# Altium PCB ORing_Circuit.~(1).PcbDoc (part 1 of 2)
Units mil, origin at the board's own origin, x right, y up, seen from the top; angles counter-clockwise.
Board outline 1338.58 x 1378.07 mil, 8 copper layers (Top Layer, Layer 2, Layer 3, Layer 4, Layer 5, Layer 6, Layer 7, Bottom Layer), stack 50.047 mil thick; 34 components, 15 nets, 290 pads, 1023 vias.
Unrouted connection lines stored in the file: 1.
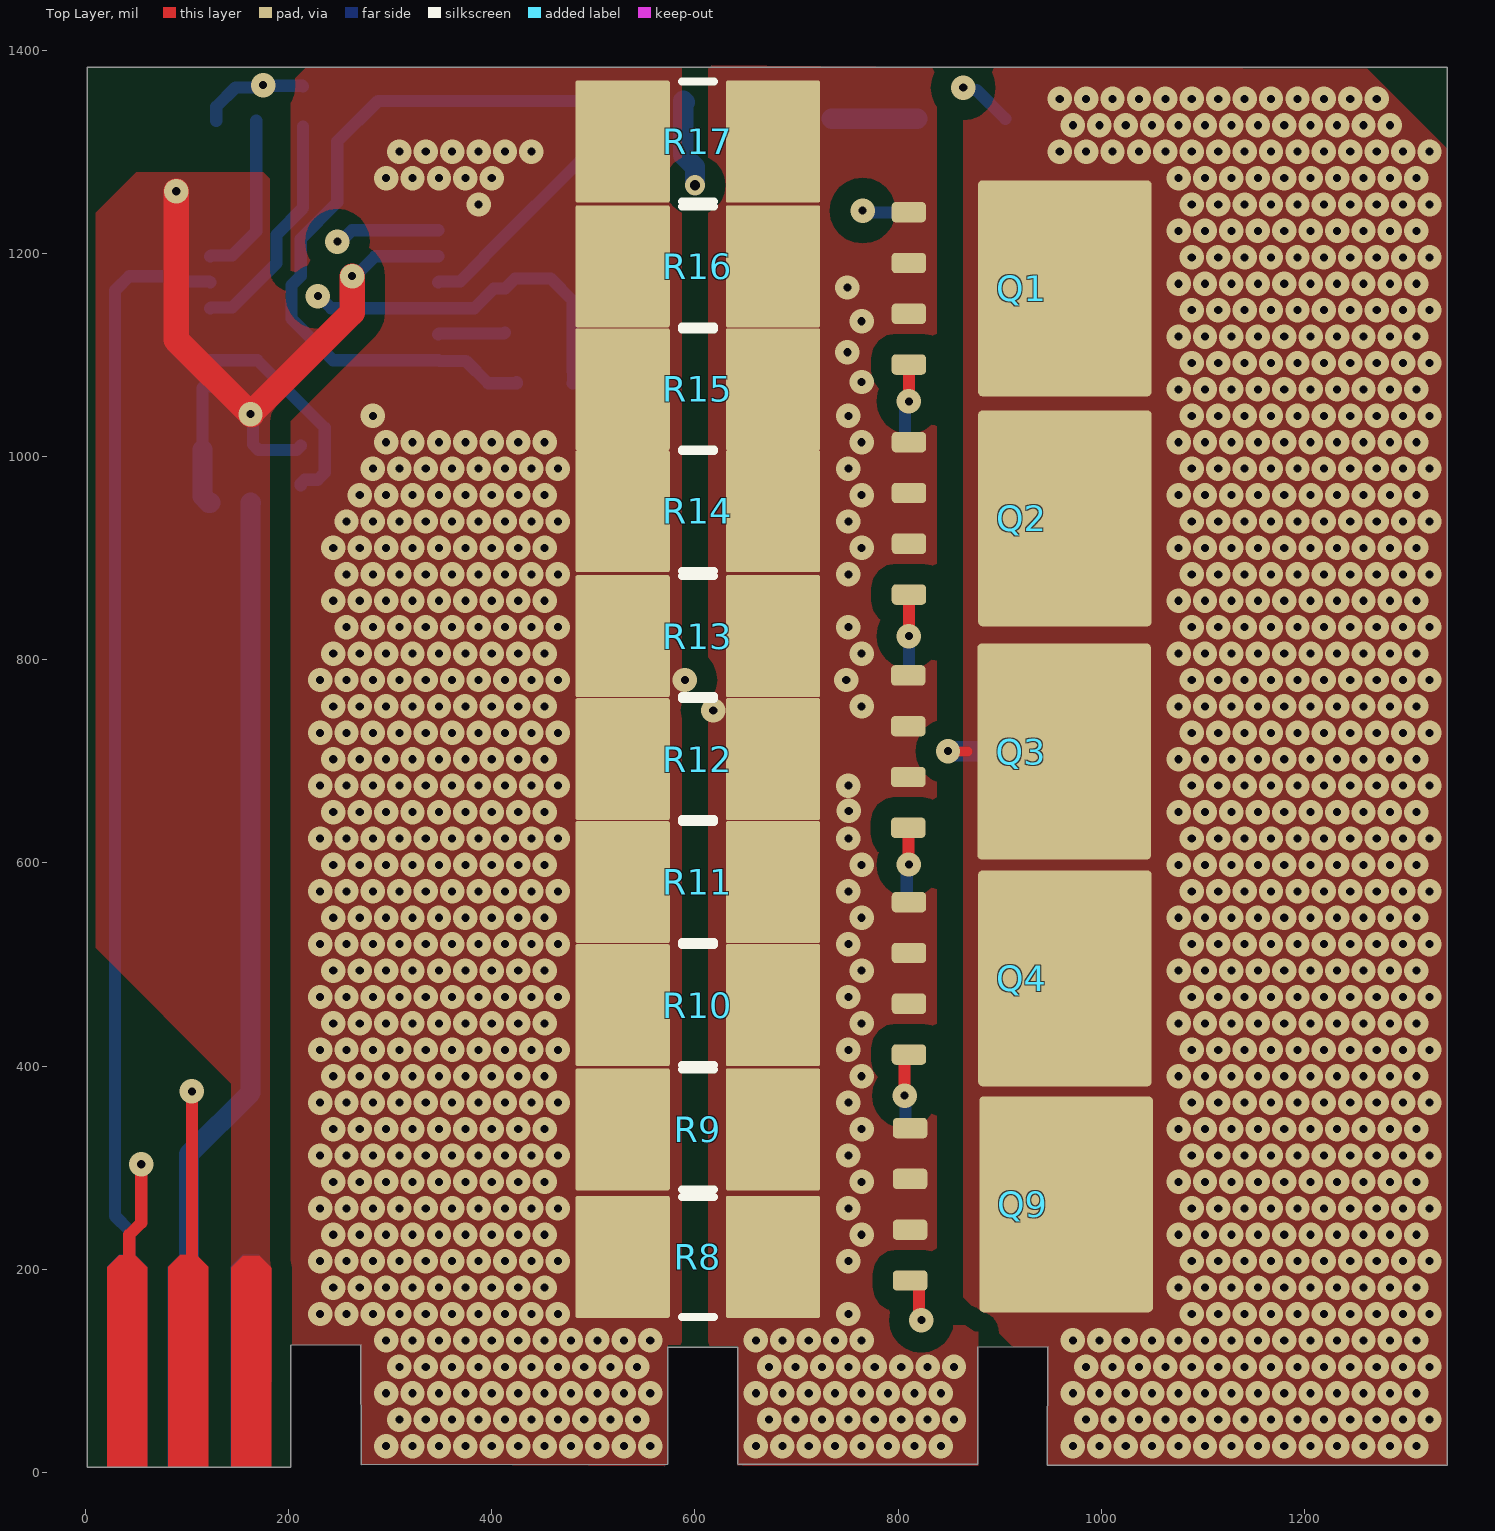
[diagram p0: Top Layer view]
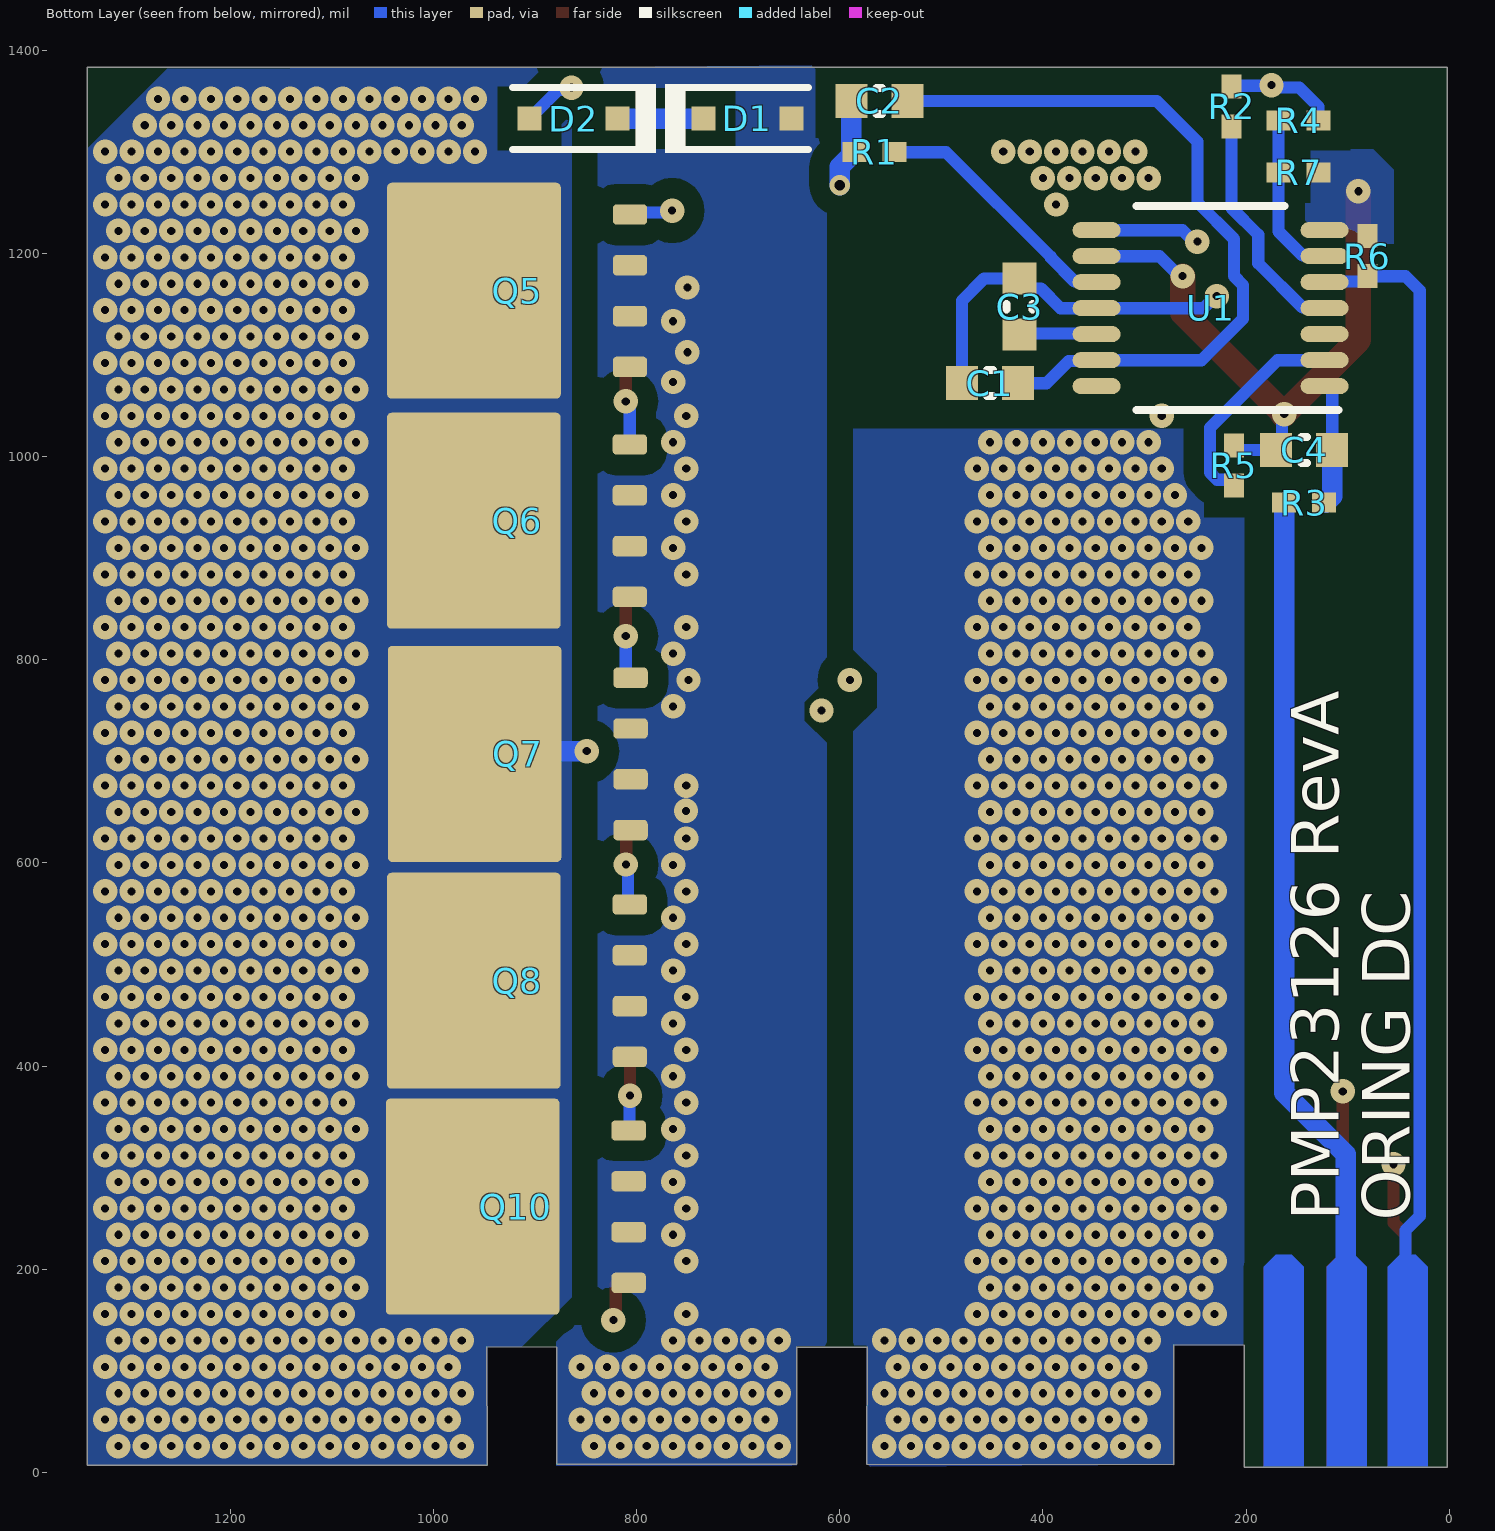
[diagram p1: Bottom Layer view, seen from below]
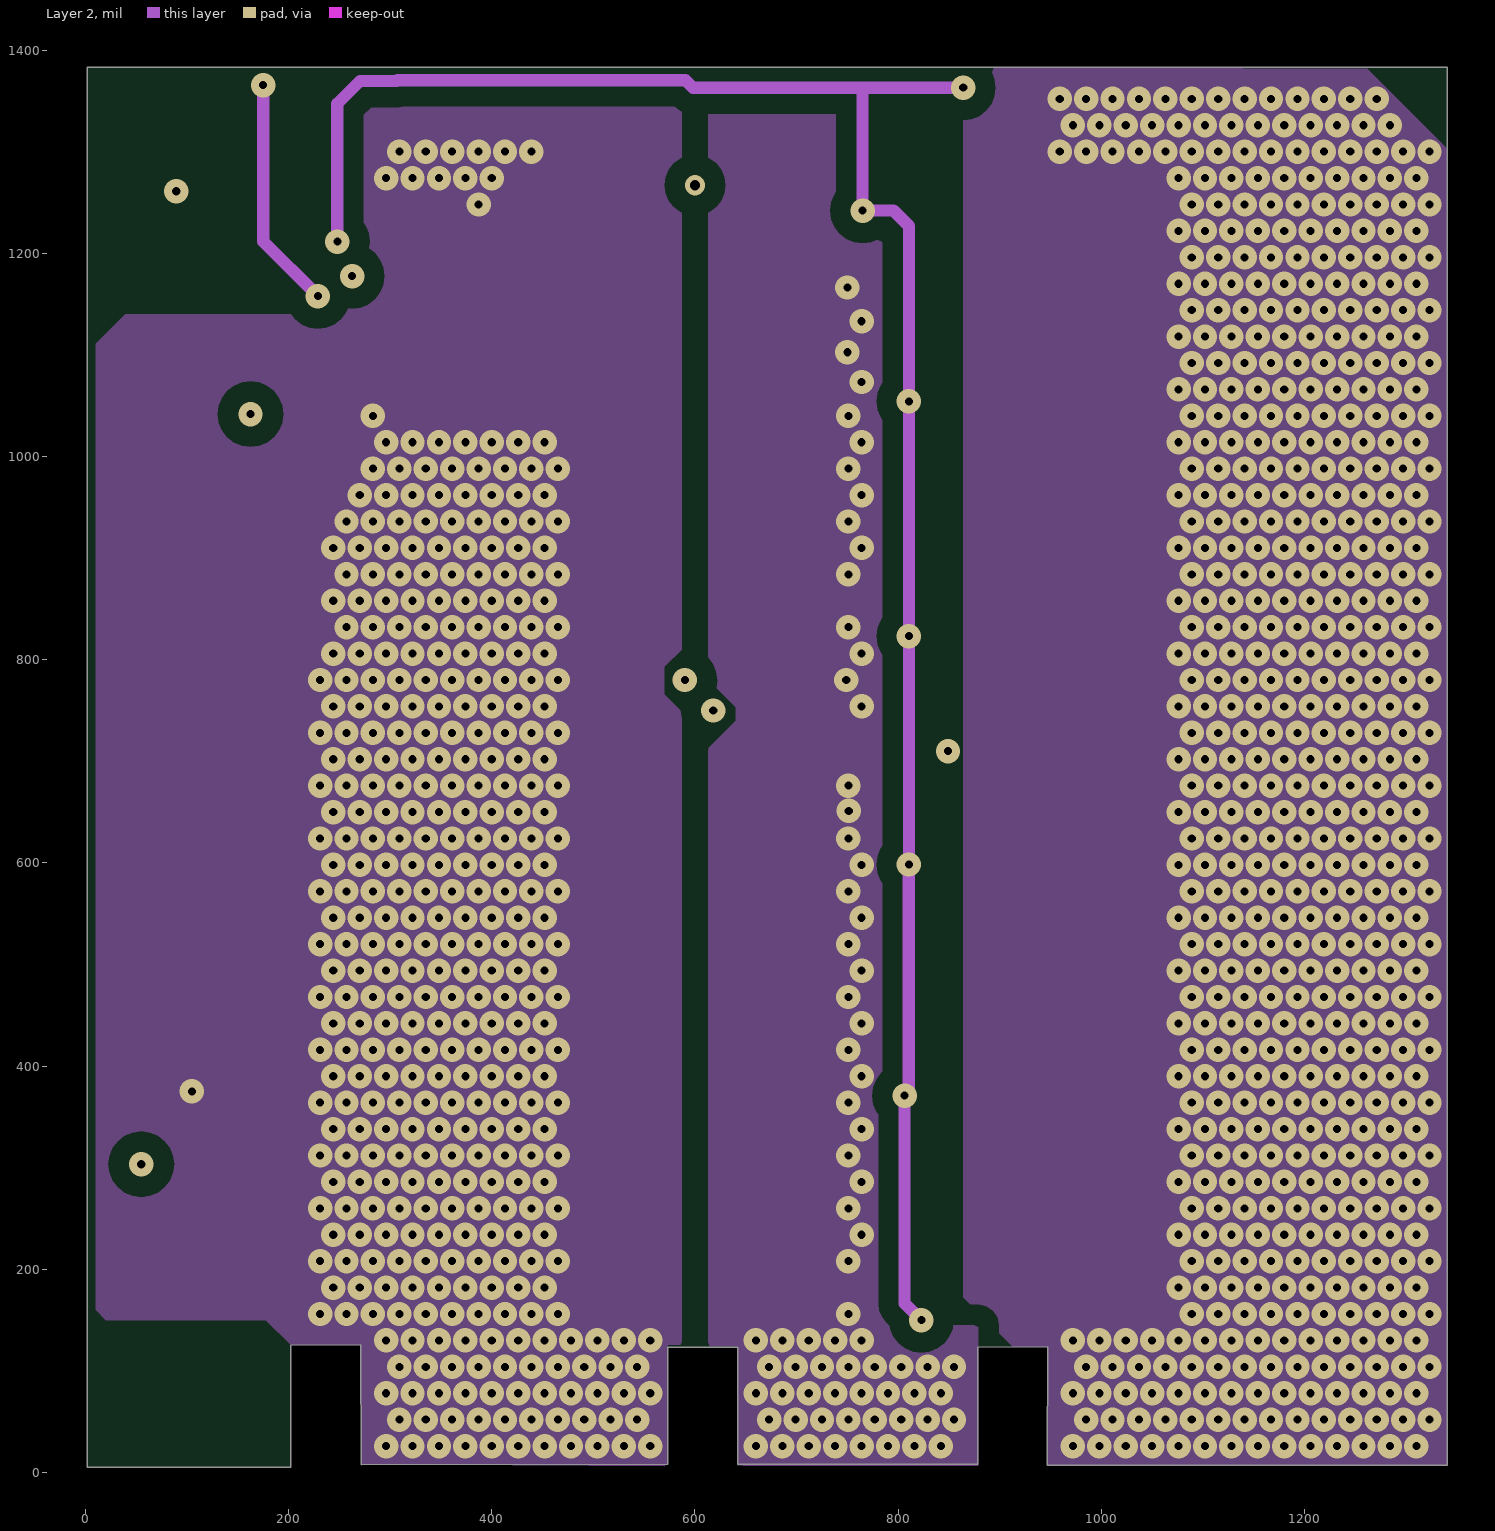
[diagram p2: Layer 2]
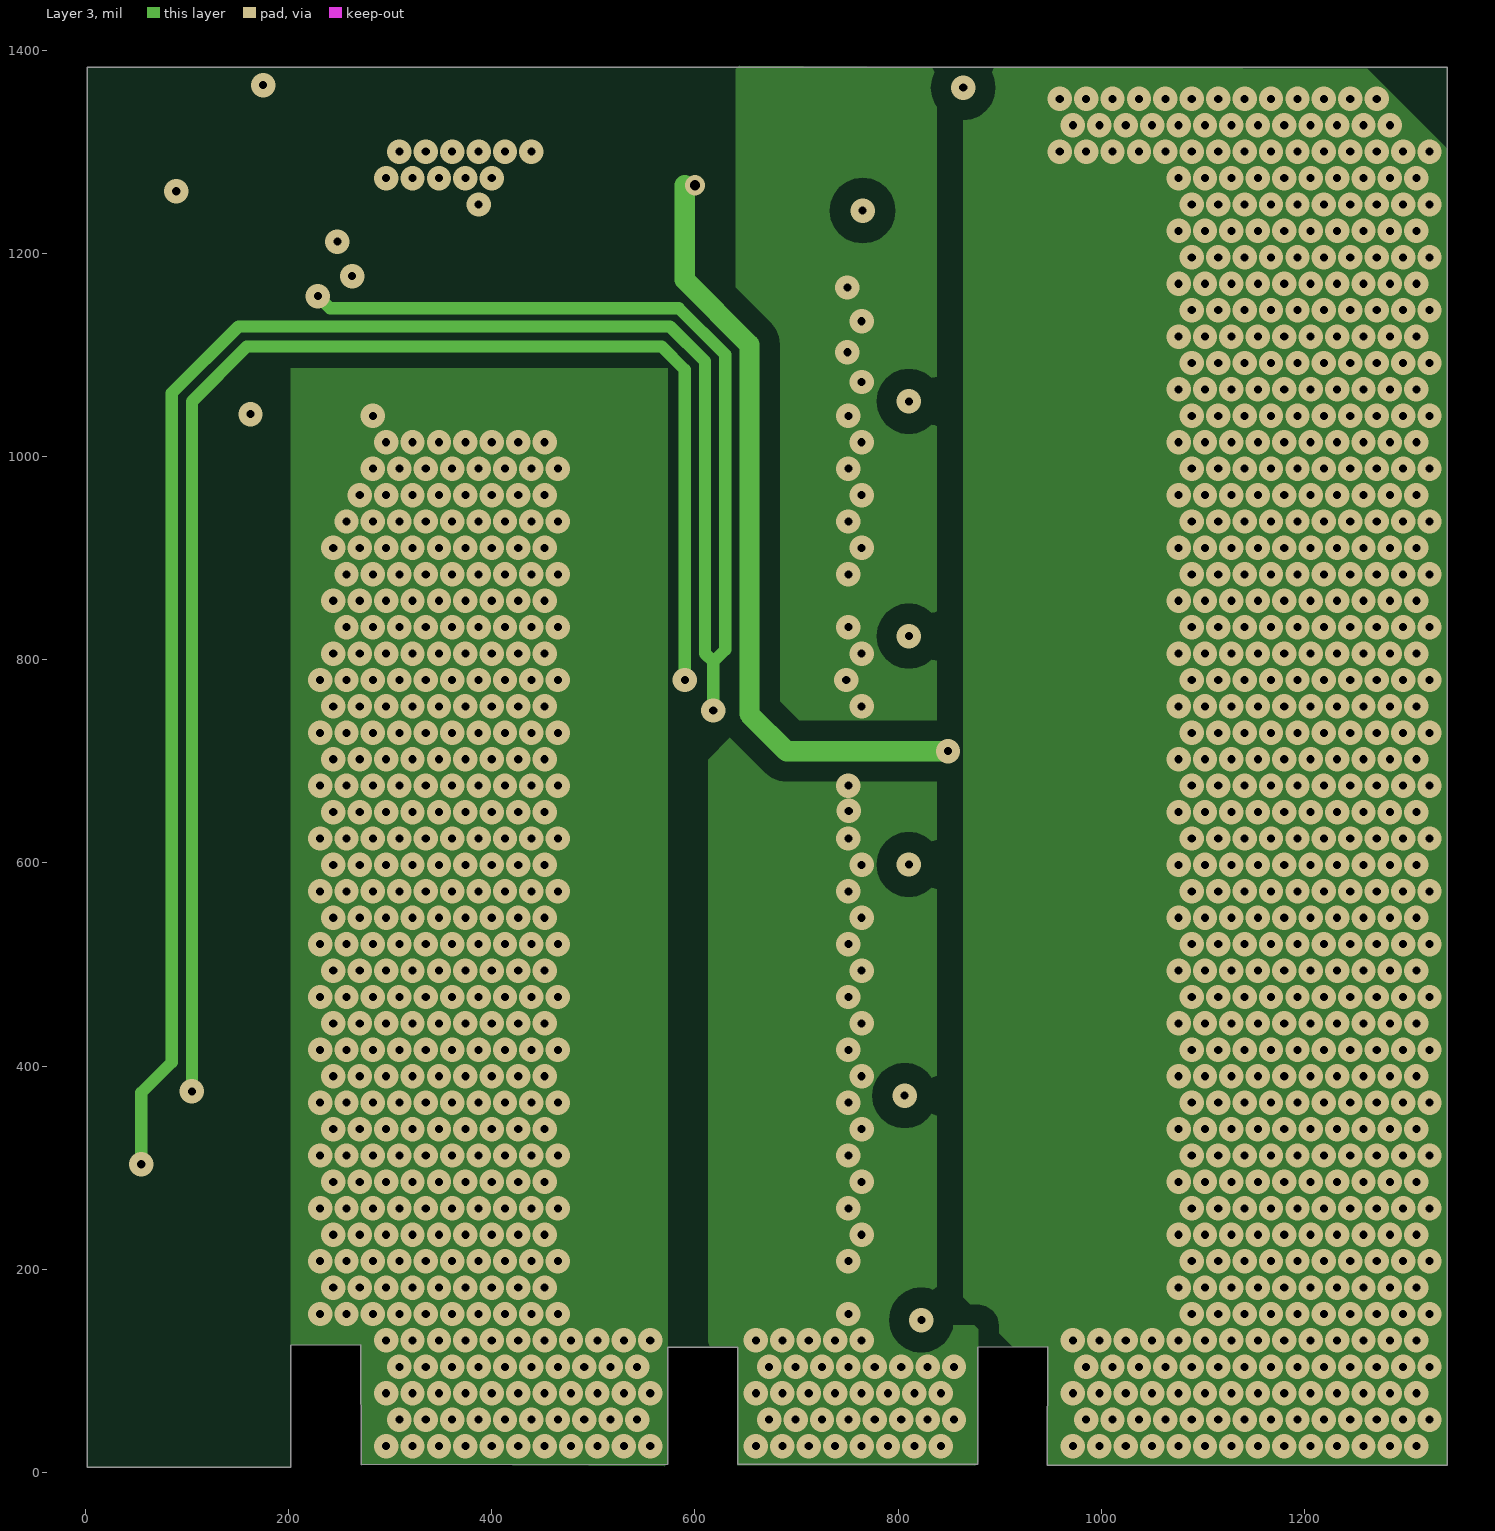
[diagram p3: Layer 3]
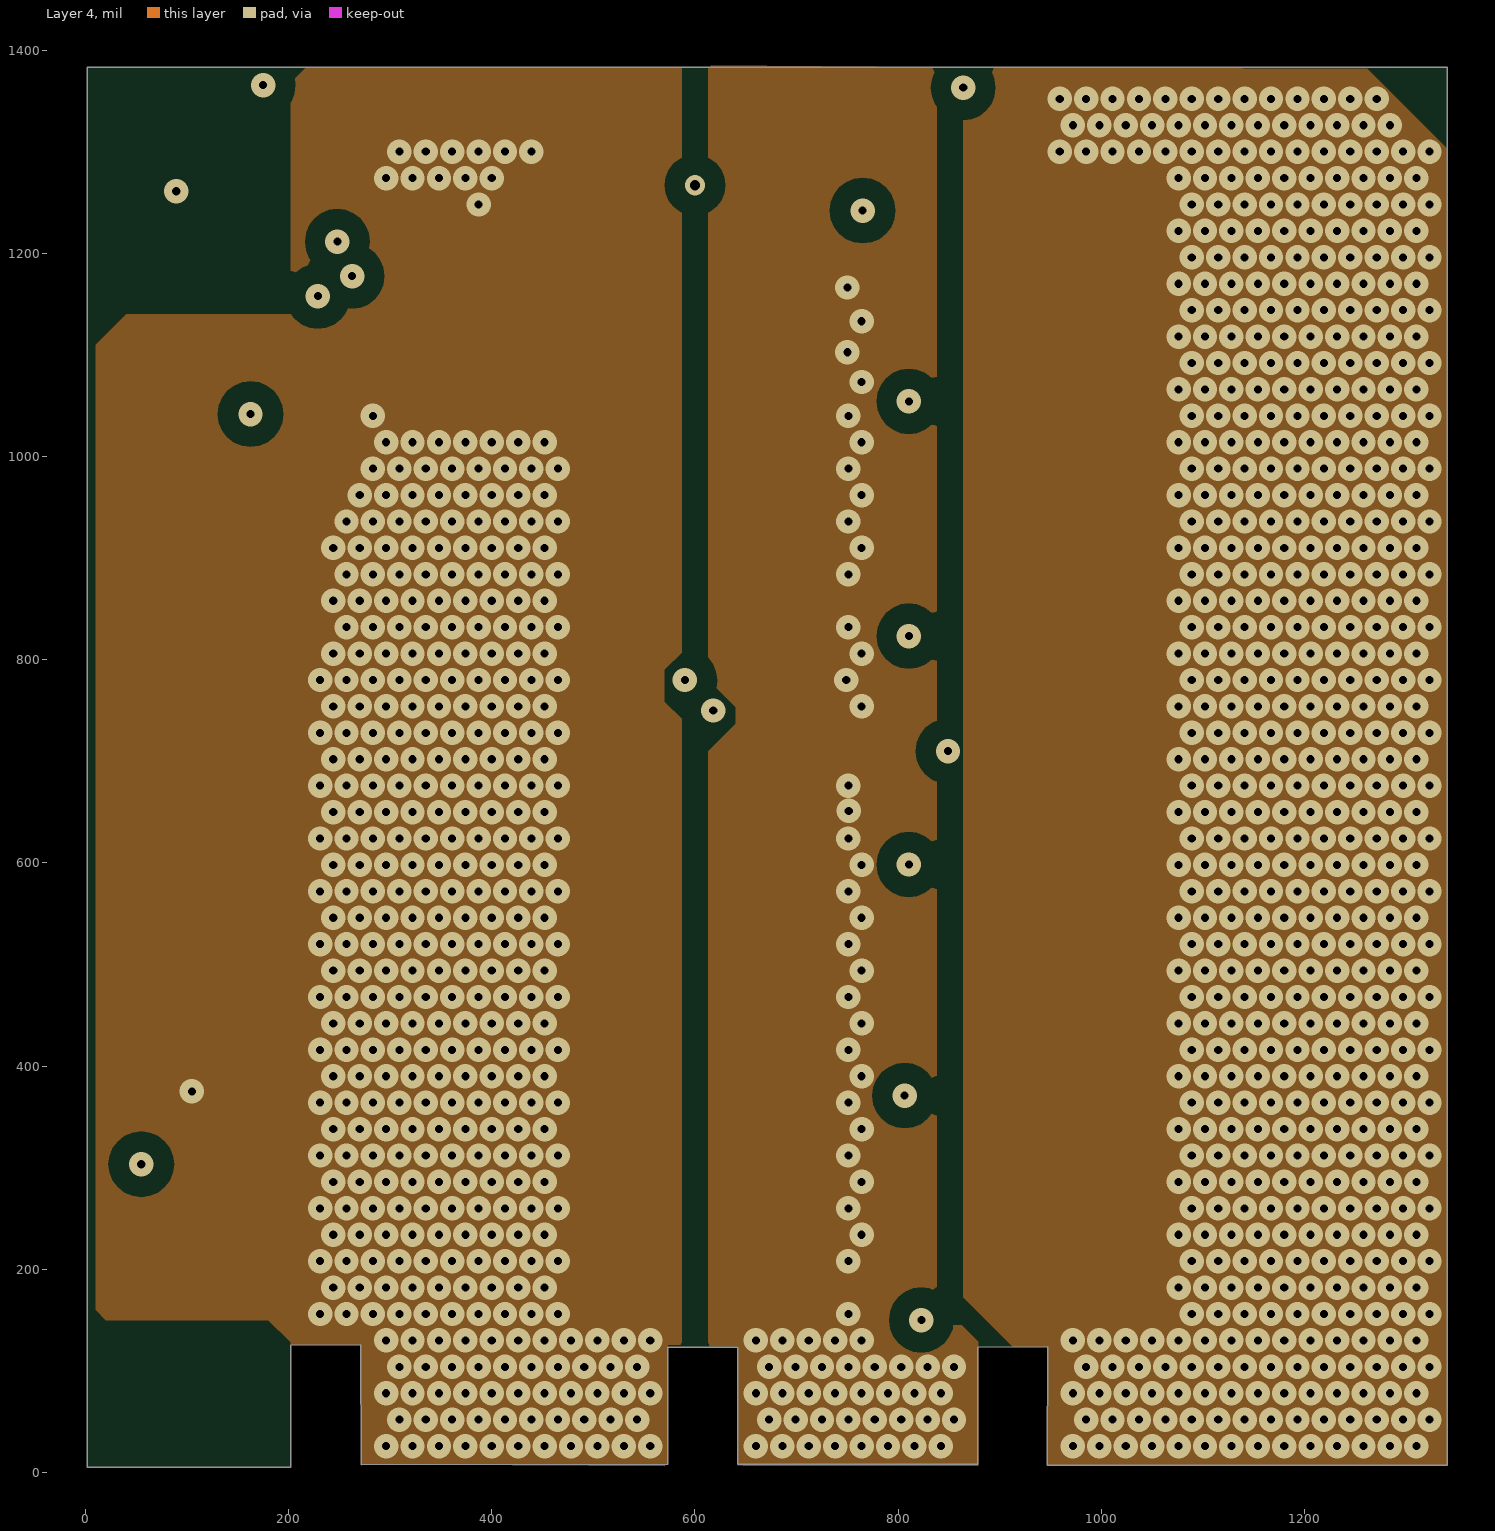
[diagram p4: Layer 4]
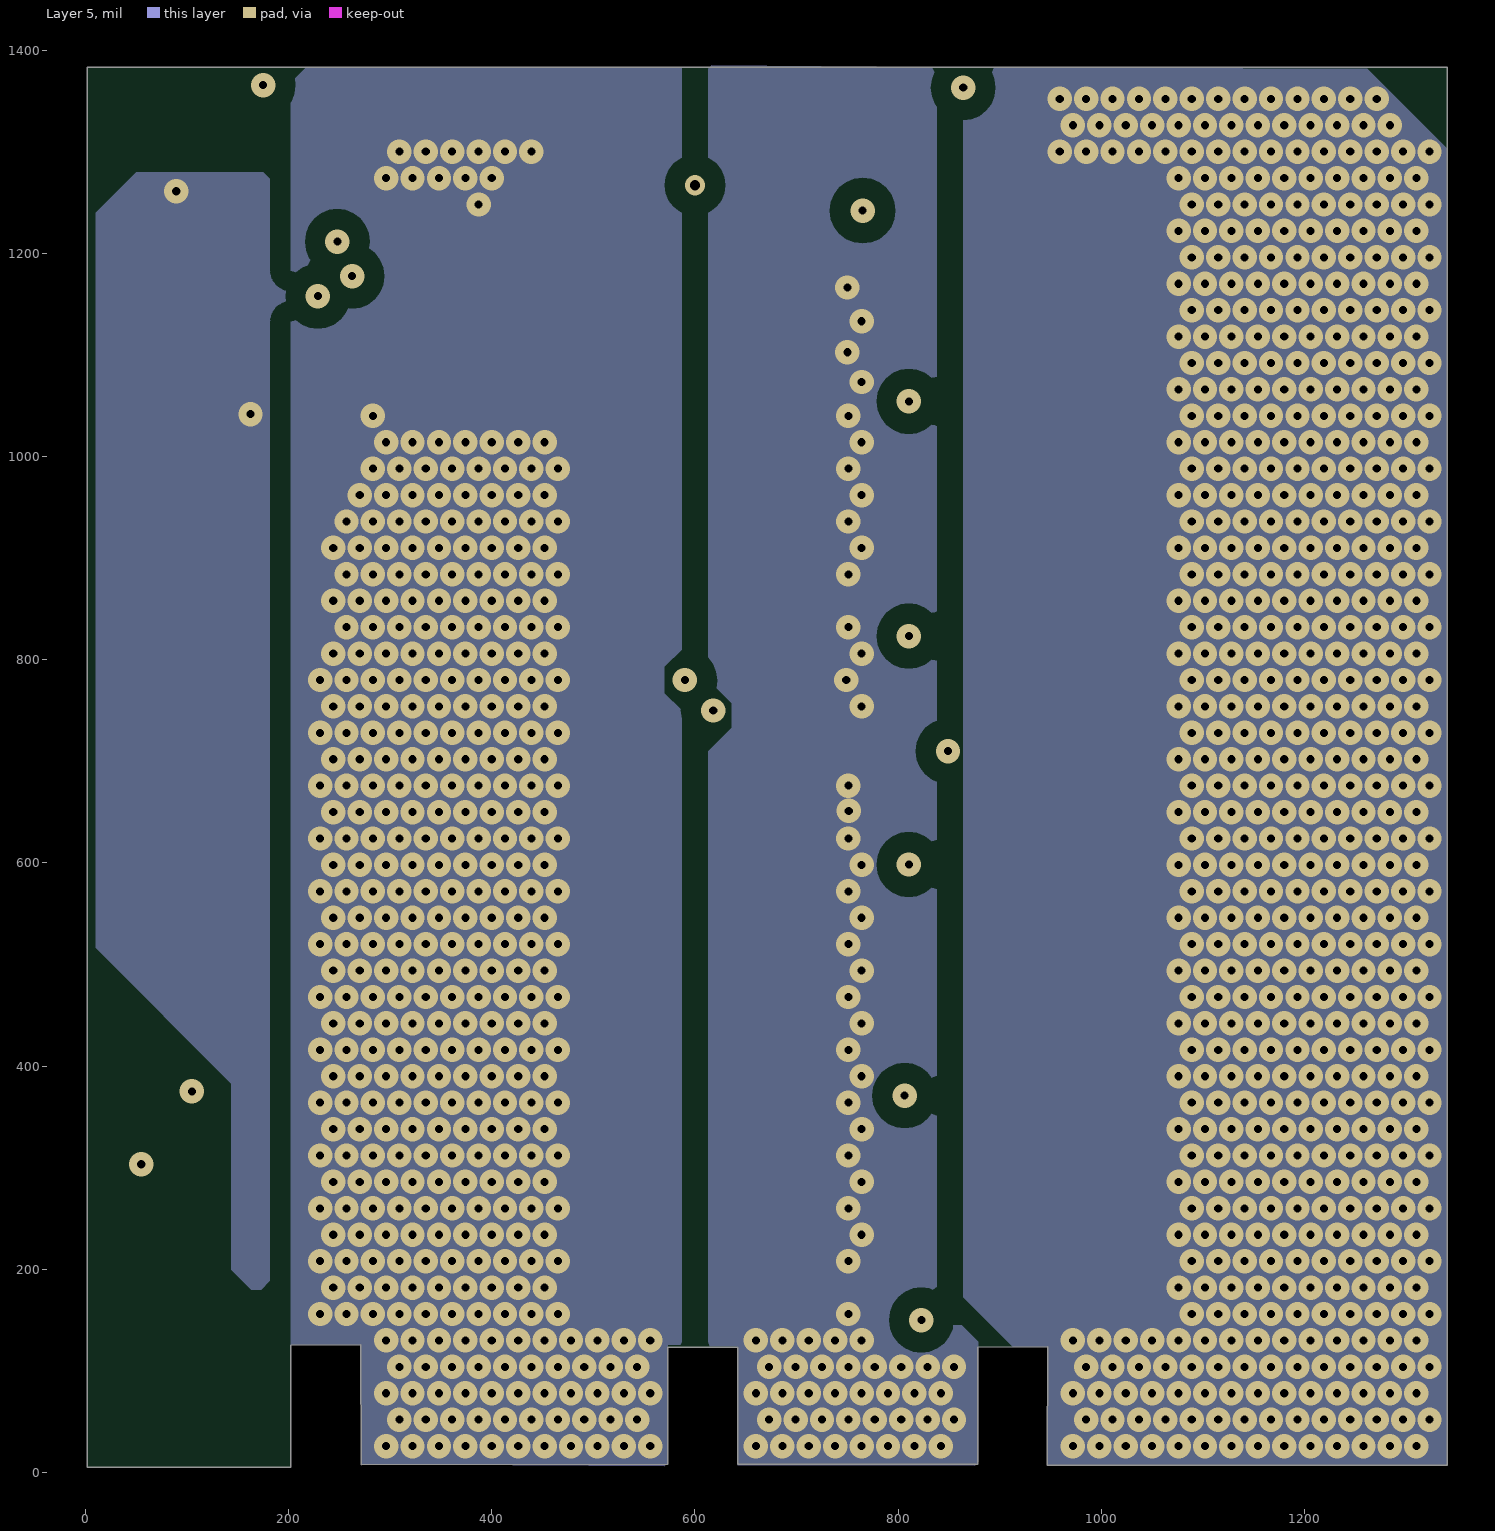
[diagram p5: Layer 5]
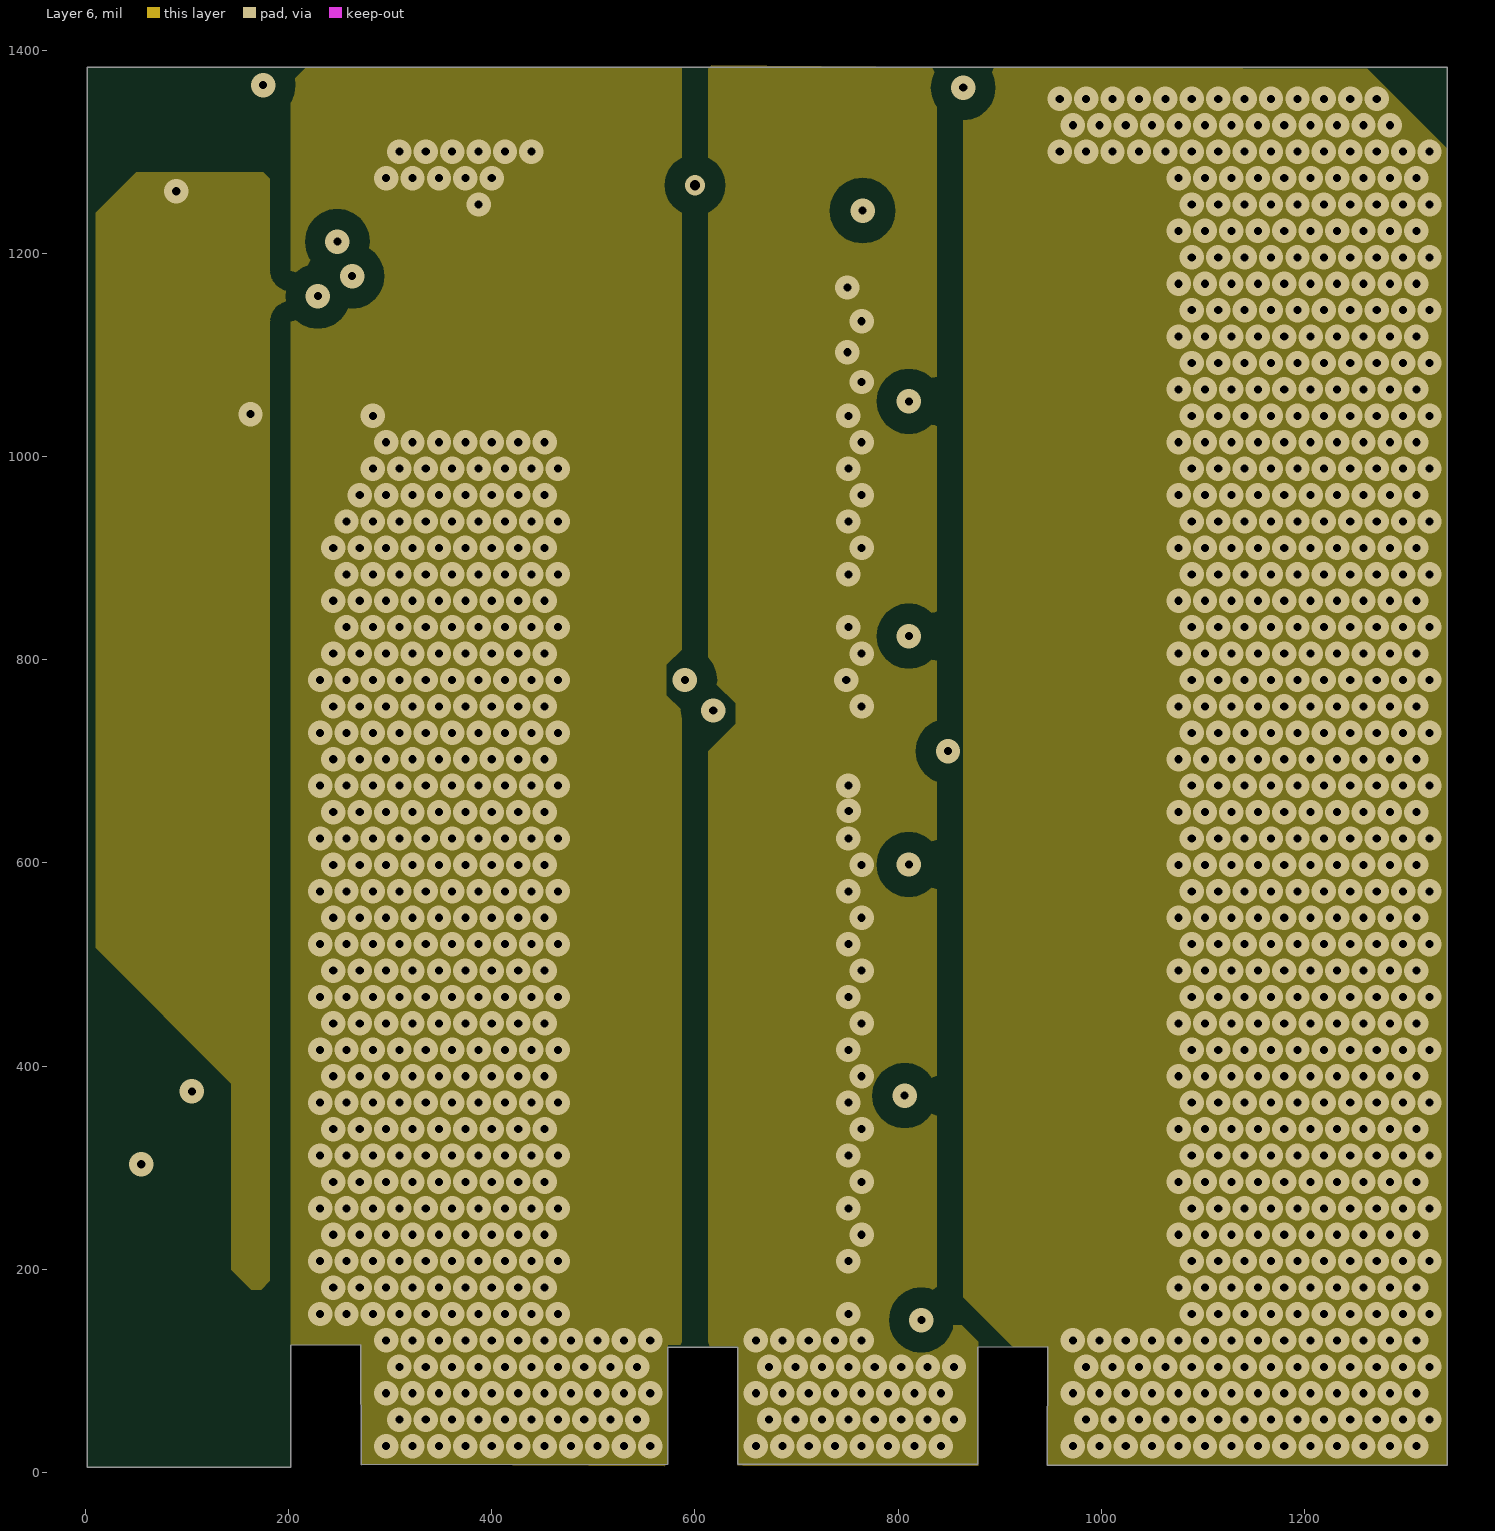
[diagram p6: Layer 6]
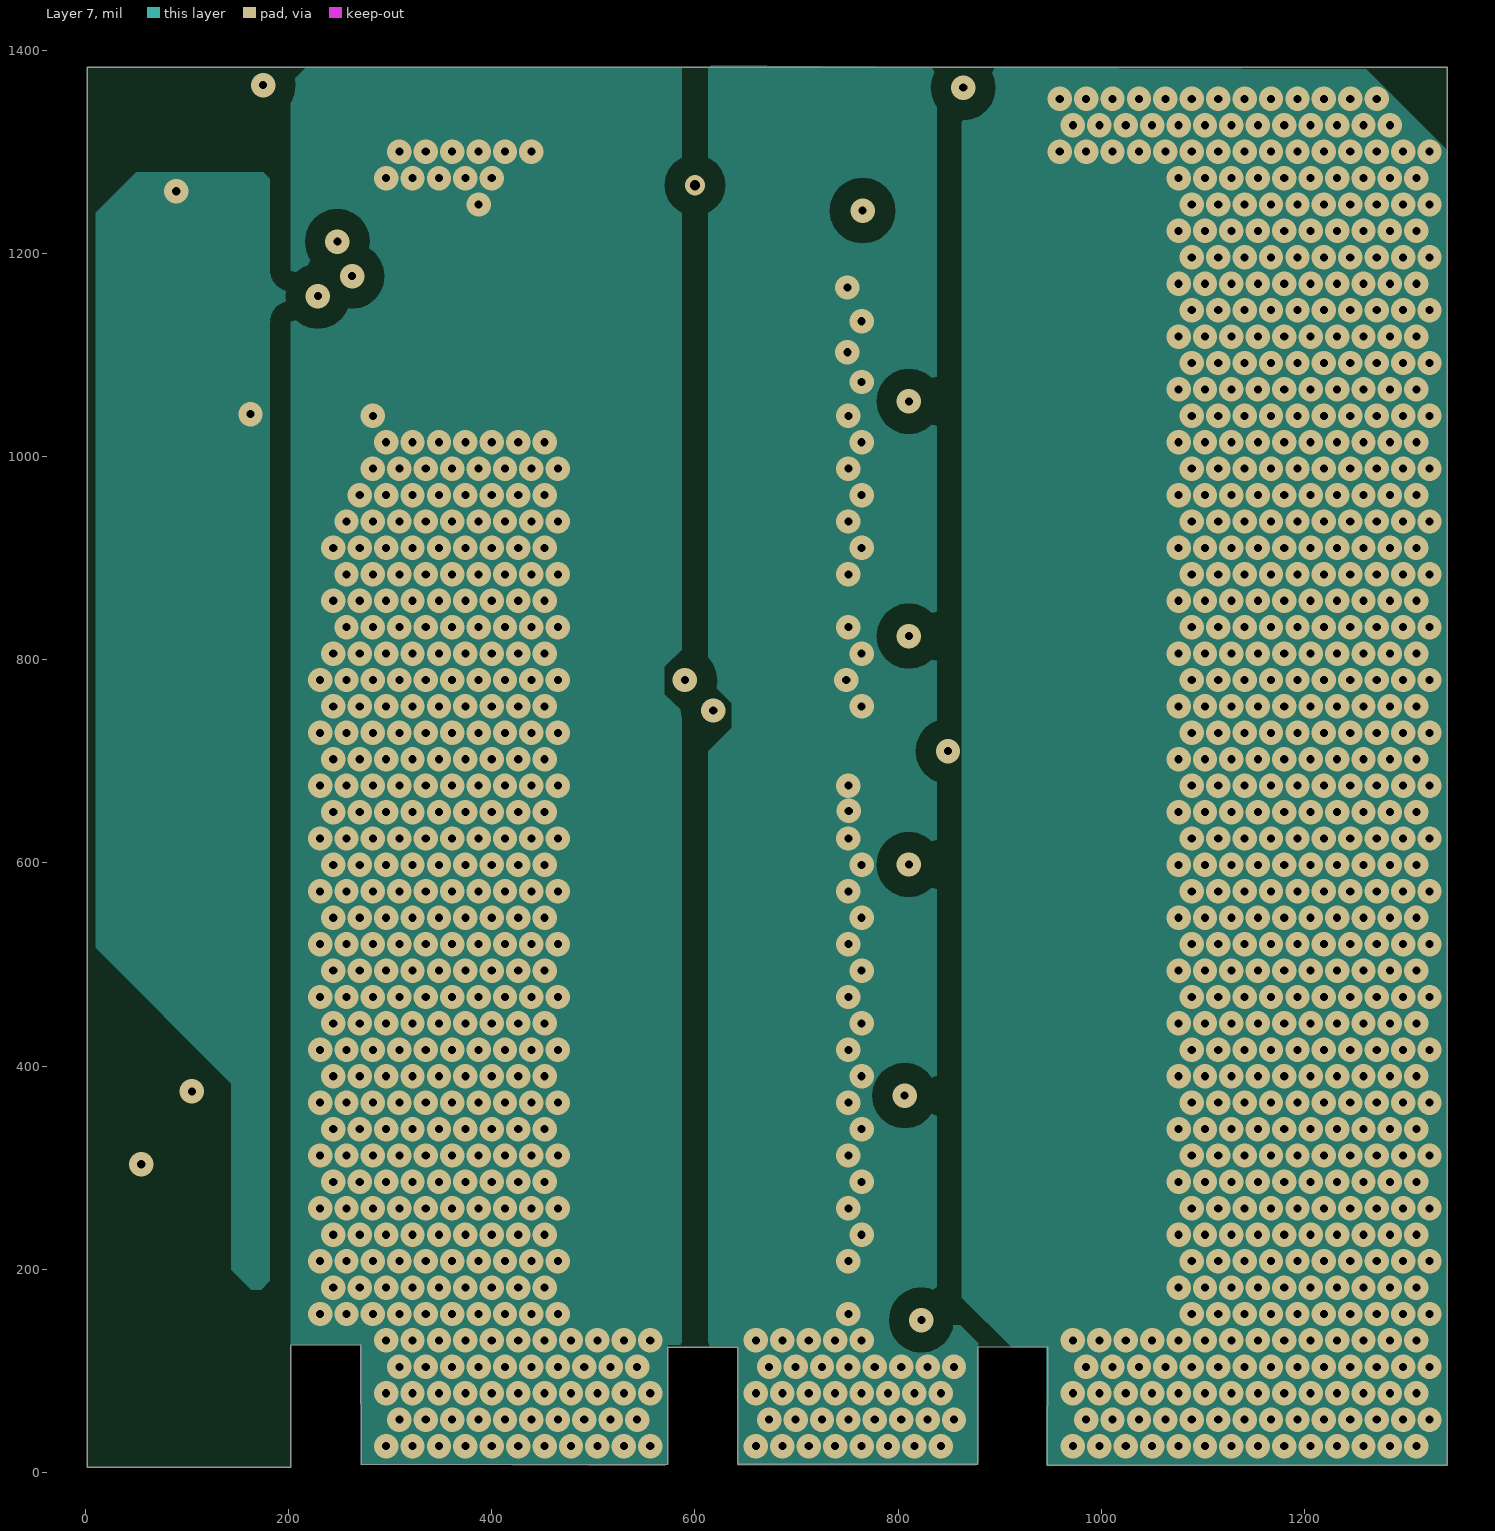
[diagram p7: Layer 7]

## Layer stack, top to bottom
Top Solder: solder mask 0.4, Solder Resist, Dk 3.5
Top Layer: signal copper 2.7559
Dielectric 1: core 4, Core-009, Dk 4.5
Layer 2: signal copper 2.7559
Dielectric 3: core 4, Core-009, Dk 4.5
Layer 3: signal copper 2.7559
Dielectric 5: core 4, Core-009, Dk 4.5
Layer 4: signal copper 2.7559
Dielectric1: core 4, Core-009, Dk 4.5
Layer 5: signal copper 2.7559
Dielectric 6: core 4, Core-009, Dk 4.5
Layer 6: signal copper 2.7559
Dielectric 4: core 4, Core-009, Dk 4.5
Layer 7: signal copper 2.7559
Dielectric 2: core 4, Core-009, Dk 4.5
Bottom Layer: signal copper 2.7559
Bottom Solder: solder mask 0.4, Solder Resist, Dk 3.5

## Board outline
1.94,5 202,5 202,125.23 271,125.49 271.31,7.69 573.42,7.94 573.11,123.48 642.11,123.48 642.11,7.94 878.33,7.94 878.33,123.48 947.33,123.74 946.83,7.25 1340.53,7 1340.53,1383.07 1.94,1383.07

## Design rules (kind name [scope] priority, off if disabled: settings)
AcuteAngle [All] p1: minimum=4.50000000000000E+0001 checktracksonly=FALSE
AssemblyTestPointUsage [All] p1: valid=2
Clearance Clearance_2 [InNetClass('HV') vs Not InNetClass('HV')] p1: gap=60 ignorepadtopadclearanceinfootprint=TRUE except(0: Arc-Hole Track-Hole SMDPad-Hole THPad-Hole Via-Hole Fill-Hole Poly-Hole Region-Hole Text-Hole)
Clearance Clearance_1 [InNetClass('MV') vs Not InNetClass('MV')] p2: gap=40 ignorepadtopadclearanceinfootprint=TRUE
Clearance Clearance_Keepouts [((IsTrack Or IsArc) And Not InPoly) And IsFree and IsKeepOut vs ((IsTrack Or IsArc) And Not InPoly) And IsFree and IsKeepOut] p3: gap=0 ignorepadtopadclearanceinfootprint=FALSE
Clearance Clearance_BoardEdge_MountingHoles [OnCopper and InComponentClass('Mounting Holes') vs IsKeepOut] p4: gap=40 ignorepadtopadclearanceinfootprint=FALSE except(0: Arc-Hole Track-Hole SMDPad-Hole THPad-Hole Via-Hole Fill-Hole Poly-Hole Region-Hole Text-Hole)
Clearance Clearance_BoardEdge_Poly [OnCopper and InPoly vs IsKeepOut] p5: gap=25 ignorepadtopadclearanceinfootprint=FALSE except(0: Arc-Hole Track-Hole SMDPad-Hole THPad-Hole Via-Hole Fill-Hole Poly-Hole Region-Hole Text-Hole)
Clearance Clearance_BoardEdge [OnCopper and Not InComponentClass('Logo') and not InComponentClass('FiducialMark') and not InRegion(1000,500,4000,800) and Not IsKeepout vs IsKeepOut] p6: gap=75 ignorepadtopadclearanceinfootprint=FALSE except(0: Arc-Hole Track-Hole SMDPad-Hole THPad-Hole Via-Hole Fill-Hole Poly-Hole Region-Hole Text-Hole)
Clearance Clearance_Poly [InPolygon] p7: gap=20 ignorepadtopadclearanceinfootprint=FALSE except(0: Arc-Hole Track-Hole SMDPad-Hole THPad-Hole Via-Hole Fill-Hole Poly-Hole Region-Hole Text-Hole)
Clearance [All] p8: gap=7.87 ignorepadtopadclearanceinfootprint=FALSE except(0: Arc-SMDPad Arc-Hole Track-Hole SMDPad-Hole THPad-Hole Via-Hole Fill-Hole Poly-Hole Region-Hole Text-Hole)
ComponentClearance ComponentClearance_MountingHoles_FiducialMarks [InComponentClass('Mounting Holes') vs InComponentClass('FiducialMark')] p1: gap=20 collisioncheckmode=3 verticalgap=7 showdistances=FALSE
ComponentClearance ComponentClearance_Shunt [InComponentClass('Header') vs InComponentClass('Shunt')] p2: gap=0 collisioncheckmode=3 verticalgap=0 showdistances=FALSE
ComponentClearance ComponentClearance_Logo [InComponentClass('Logo')] p3: gap=5 collisioncheckmode=3 verticalgap=10 showdistances=FALSE
ComponentClearance ComponentClearance_ScrewToNut [(HasFootprint('KEYSTONE_4824')) vs (HasFootprint('Keystone_1903C'))] p4: gap=0 collisioncheckmode=3 verticalgap=0 showdistances=FALSE
ComponentClearance ComponentClearance_MountingHoles [InComponentClass('Mounting Holes')] p5: gap=20 collisioncheckmode=3 verticalgap=7 showdistances=FALSE
ComponentClearance ComponentClearance_SmallPassives [HasFootprint('0201*') or HasFootprint('0402*') or HasFootprint('0508') or HasFootprint('0603*') or HasFootprint('0612') or HasFootprint('0805*') or HasFootprint('0815*') or HasFootprint('0830*') or HasFootprint('1206*') or HasFootprint('1210*') or HasFootprint('1808*') or HasFootprint('1812*') or HasFootprint('1825*') or HasFootprint('2010*') or HasFootprint('2220*') or HasFootprint('2225*') or HasFootprint('2512*') or HasFootprint('2728*') or HasFootprint('3518*') vs HasFootprint('0201*') or HasFootprint('0402*') or HasFootprint('0508') or HasFootprint('0603*') or HasFootprint('0612') or HasFootprint('0805*') or HasFootprint('0815*') or HasFootprint('0830*') or HasFootprint('1206*') or HasFootprint('1210*') or HasFootprint('1808*') or HasFootprint('1812*') or HasFootprint('1825*') or HasFootprint('2010*') or HasFootprint('2220*') or HasFootprint('2225*') or HasFootprint('2512*') or HasFootprint('2728*') or HasFootprint('3518*')] p6: gap=20 collisioncheckmode=3 verticalgap=20 showdistances=FALSE
ComponentClearance ComponentClearance_THtoSMT [IsThruComponent vs IsSMTComponent] p7: gap=10 collisioncheckmode=3 verticalgap=7 showdistances=FALSE
ComponentClearance ComponentClearance_THtoTH [IsThruComponent vs IsThruComponent] p8: gap=10 collisioncheckmode=3 verticalgap=7 showdistances=FALSE
ComponentClearance [All] p9: gap=10 collisioncheckmode=3 verticalgap=7 showdistances=FALSE
DiffPairsRouting [All] p1: maxlimit=100 minlimit=10 mostfreqgap=10 toplayer_minwidth=15 toplayer_maxwidth=15 toplayer_prefwidth=15 midlayer1_minwidth=15 midlayer1_maxwidth=15 midlayer1_prefwidth=15 midlayer2_minwidth=15 midlayer2_maxwidth=15 midlayer2_prefwidth=15 midlayer3_minwidth=15 midlayer3_maxwidth=15 midlayer3_prefwidth=15 midlayer4_minwidth=15 midlayer4_maxwidth=15 midlayer4_prefwidth=15 midlayer5_minwidth=15 midlayer5_maxwidth=15 midlayer5_prefwidth=15 midlayer6_minwidth=15 midlayer6_maxwidth=15 midlayer6_prefwidth=15 bottomlayer_minwidth=15 bottomlayer_maxwidth=15 bottomlayer_prefwidth=15 maxuncoupledlength=1000
FabricationTestPointUsage TestPointUsage [All] p1: valid=2 allowmultiple=FALSE
FabricationTestpoint Testpoint [All] p1: side=3 testpointundercomponent=TRUE minsize=40 maxsize=100 preferedsize=60 minholesize=0 maxholesize=40 preferedholesize=32 testpointgrid=1 allowsidetop=TRUE allowsidebottom=TRUE usegrid=TRUE gridtolerance=0.01
FanoutControl Fanout_LCC [IsLCC] p1: bgadir=Out bgaviamode=Centered fanoutstyle=Auto fanoutdirection=Alternating viagrid=1 // Fanout_LCC (Default Rule)
FanoutControl Fanout_BGA [IsBGA] p2: bgadir=Out bgaviamode=Centered fanoutstyle=Auto fanoutdirection=Alternating viagrid=1 // Fanout_BGA (Default Rule)
FanoutControl Fanout_Default [All] p4: bgadir=Out bgaviamode=Centered fanoutstyle=Auto fanoutdirection=Alternating viagrid=1 // Fanout_Default (Default Rule)
FanoutControl Fanout_Small [(CompPinCount < 5)] p5: bgadir=Out bgaviamode=Centered fanoutstyle=Auto fanoutdirection=OutThenIn viagrid=1 // Fanout_Small (Default Rule)
Height [All] p1: minheight=0 maxheight=3000 prefheight=500
HoleSize [All] p1: absolutevalues=TRUE maxlimit=501 minlimit=7 maxpercent=80.000 minpercent=20.000
MinimumAnnularRing MinimumAnnularRing_ThermalPadVias [IsVia and InAnyComponent] p1: minimumring=5.91
MinimumAnnularRing [All] p2: minimumring=5
MinimumSolderMaskSliver MinimumSolderMaskSliver_Logo [InComponentClass('Logo') vs InComponentClass('Logo')] p1: minsoldermaskwidth=0.7
MinimumSolderMaskSliver [All] p2: minsoldermaskwidth=1
PlaneConnect [All] p1: planeconnectstyle=Direct reliefexpansion=10 reliefentries=4 reliefconductorwidth=10 reliefairgap=10
PolygonConnect PolygonConnect_16 [All vs IsNamedPolygon('C106_2') Or  IsNamedPolygon('Vout') Or  IsNamedPolygon('IN+') Or  IsNamedPolygon('Q203_5') Or  IsNamedPolygon('IN+') Or  IsNamedPolygon('Q201_5') Or  IsNamedPolygon('C108_2') Or  IsNamedPolygon('SGND') Or  IsNamedPolygon('IN+') Or  IsNamedPolygon('SGND') Or  IsNamedPolygon('Q203_5') Or  IsNamedPolygon('IN+') Or  IsNamedPolygon('SGND') Or  IsNamedPolygon('GND') Or  IsNamedPolygon('C113_2') Or  IsNamedPolygon('C107_2') Or  IsNamedPolygon('C107_2') Or  IsNamedPolygon('Vout') Or  IsNamedPolygon('SIGNAL_LAYER_1_GND_P074') Or  IsNamedPolygon('HV') Or  IsNamedPolygon('C108_2') Or  IsNamedPolygon('C103_2') Or  IsNamedPolygon('Q201_5') Or  IsNamedPolygon('Vout') Or  IsNamedPolygon('C109_2') Or  IsNamedPolygon('Q201_5') Or  IsNamedPolygon('GND') Or  IsNamedPolygon('C107_2') Or  IsNamedPolygon('C102_1') Or  IsNamedPolygon('GND') Or  IsNamedPolygon('SGND') Or  IsNamedPolygon('HS') Or  IsNamedPolygon('Q203_5') Or  IsNamedPolygon('Q201_5') Or  IsNamedPolygon('Q203_5')] p1: connectstyle=Direct reliefconductorwidth=10 reliefentries=4 polygonreliefangle="90 Angle" airgapwidth=10
PolygonConnect PolygonConnect_15 [All vs IsNamedPolygon('C109_2') Or  IsNamedPolygon('C107_2') Or  IsNamedPolygon('HV') Or  IsNamedPolygon('Q203_5') Or  IsNamedPolygon('C107_2') Or  IsNamedPolygon('HS') Or  IsNamedPolygon('Q201_5') Or  IsNamedPolygon('Q203_5') Or  IsNamedPolygon('C106_2') Or  IsNamedPolygon('C108_2') Or  IsNamedPolygon('Vout') Or  IsNamedPolygon('Q203_5') Or  IsNamedPolygon('C108_2') Or  IsNamedPolygon('C113_2') Or  IsNamedPolygon('Q203_5') Or  IsNamedPolygon('Q201_5') Or  IsNamedPolygon('C107_2') Or  IsNamedPolygon('C102_1') Or  IsNamedPolygon('SGND') Or  IsNamedPolygon('GND') Or  IsNamedPolygon('SGND') Or  IsNamedPolygon('GND') Or  IsNamedPolygon('IN+') Or  IsNamedPolygon('IN+') Or  IsNamedPolygon('Q201_5') Or  IsNamedPolygon('Q201_5') Or  IsNamedPolygon('SGND') Or  IsNamedPolygon('SGND') Or  IsNamedPolygon('Vout') Or  IsNamedPolygon('Vout') Or  IsNamedPolygon('IN+') Or  IsNamedPolygon('GND') Or  IsNamedPolygon('IN+') Or  IsNamedPolygon('GND')] p2: connectstyle=Direct reliefconductorwidth=10 reliefentries=4 polygonreliefangle="90 Angle" airgapwidth=10
PolygonConnect PolygonConnect_14 [All vs IsNamedPolygon('C106_2') Or  IsNamedPolygon('C107_2') Or  IsNamedPolygon('C107_2') Or  IsNamedPolygon('C107_2') Or  IsNamedPolygon('C102_1') Or  IsNamedPolygon('Q203_5') Or  IsNamedPolygon('Vout') Or  IsNamedPolygon('Q203_5') Or  IsNamedPolygon('Q203_5') Or  IsNamedPolygon('Q201_5') Or  IsNamedPolygon('C108_2') Or  IsNamedPolygon('Q203_5') Or  IsNamedPolygon('HS') Or  IsNamedPolygon('HV') Or  IsNamedPolygon('C108_2') Or  IsNamedPolygon('Q201_5') Or  IsNamedPolygon('C109_2') Or  IsNamedPolygon('Q201_5') Or  IsNamedPolygon('Q201_5') Or  IsNamedPolygon('C113_2')] p3: connectstyle=Direct reliefconductorwidth=10 reliefentries=4 polygonreliefangle="90 Angle" airgapwidth=10
PolygonConnect PolygonConnect_13 [All vs IsNamedPolygon('C102_1') Or  IsNamedPolygon('HV') Or  IsNamedPolygon('C107_2') Or  IsNamedPolygon('C109_2') Or  IsNamedPolygon('C107_2') Or  IsNamedPolygon('C108_2') Or  IsNamedPolygon('C106_2') Or  IsNamedPolygon('C108_2') Or  IsNamedPolygon('C113_2') Or  IsNamedPolygon('C107_2')] p4: connectstyle=Direct reliefconductorwidth=10 reliefentries=4 polygonreliefangle="90 Angle" airgapwidth=10
PolygonConnect PolygonConnect_12 [All vs IsNamedPolygon('C107_2') Or  IsNamedPolygon('C113_2') Or  IsNamedPolygon('C106_2') Or  IsNamedPolygon('C107_2') Or  IsNamedPolygon('C107_2') Or  IsNamedPolygon('C102_1')] p5: connectstyle=Direct reliefconductorwidth=10 reliefentries=4 polygonreliefangle="90 Angle" airgapwidth=10
PolygonConnect PolygonConnect_11 [All vs IsNamedPolygon('C106_2') Or  IsNamedPolygon('C102_1') Or  IsNamedPolygon('C107_2') Or  IsNamedPolygon('C107_2') Or  IsNamedPolygon('C107_2')] p6: connectstyle=Direct reliefconductorwidth=10 reliefentries=4 polygonreliefangle="90 Angle" airgapwidth=10
PolygonConnect PolygonConnect_10 [All vs IsNamedPolygon('C106_2')] p7: connectstyle=Direct reliefconductorwidth=10 reliefentries=4 polygonreliefangle="90 Angle" airgapwidth=10
PolygonConnect PolygonConnect_9 [All vs IsNamedPolygon('C11_1') Or  IsNamedPolygon('Vin') Or  IsNamedPolygon('Vin') Or  IsNamedPolygon('5V') Or  IsNamedPolygon('D6_2') Or  IsNamedPolygon('Q3_3') Or  IsNamedPolygon('GND2') Or  IsNamedPolygon('GND2') Or  IsNamedPolygon('GND') Or  IsNamedPolygon('Q3_4') Or  IsNamedPolygon('12V5') Or  IsNamedPolygon('GND') Or  IsNamedPolygon('12V5') Or  IsNamedPolygon('D3_1')] p8: connectstyle=Direct reliefconductorwidth=10 reliefentries=4 polygonreliefangle="90 Angle" airgapwidth=10
PolygonConnect PolygonConnect_8 [All vs IsNamedPolygon('C11_1') Or  IsNamedPolygon('Vin') Or  IsNamedPolygon('12V5') Or  IsNamedPolygon('Q3_3') Or  IsNamedPolygon('GND2') Or  IsNamedPolygon('GND2') Or  IsNamedPolygon('5V') Or  IsNamedPolygon('Q3_4') Or  IsNamedPolygon('12V5')] p9: connectstyle=Direct reliefconductorwidth=10 reliefentries=4 polygonreliefangle="90 Angle" airgapwidth=10
PolygonConnect PolygonConnect_7 [All vs IsNamedPolygon('GND2') Or  IsNamedPolygon('GND2') Or  IsNamedPolygon('5V') Or  IsNamedPolygon('12V5') Or  IsNamedPolygon('12V5') Or  IsNamedPolygon('C11_1')] p10: connectstyle=Direct reliefconductorwidth=10 reliefentries=4 polygonreliefangle="90 Angle" airgapwidth=10
PolygonConnect PolygonConnect_6 [All vs IsNamedPolygon('GND2') Or  IsNamedPolygon('SGND') Or  IsNamedPolygon('GND1') Or  IsNamedPolygon('C901_1') Or  IsNamedPolygon('SGND') Or  IsNamedPolygon('GND2') Or  IsNamedPolygon('GND1')] p11: connectstyle=Direct reliefconductorwidth=10 reliefentries=4 polygonreliefangle="90 Angle" airgapwidth=10
PolygonConnect PolygonConnect_5 [All vs IsNamedPolygon('GND1') Or  IsNamedPolygon('GND1')] p12: connectstyle=Direct reliefconductorwidth=10 reliefentries=4 polygonreliefangle="90 Angle" airgapwidth=10
PolygonConnect PolygonConnect_4 [All vs IsNamedPolygon('C21_1') Or  IsNamedPolygon('C5_1') Or  IsNamedPolygon('C12_2') Or  IsNamedPolygon('C2_2') Or  IsNamedPolygon('C13_1') Or  IsNamedPolygon('C28_1') Or  IsNamedPolygon('C6_1') Or  IsNamedPolygon('GND') Or  IsNamedPolygon('GND2') Or  IsNamedPolygon('C14_1') Or  IsNamedPolygon('C13_1') Or  IsNamedPolygon('Q1_3') Or  IsNamedPolygon('C14_1') Or  IsNamedPolygon('C5_1') Or  IsNamedPolygon('GND2') Or  IsNamedPolygon('C28_1') Or  IsNamedPolygon('D5_2') Or  IsNamedPolygon('D6_2') Or  IsNamedPolygon('D2_1') Or  IsNamedPolygon('C12_2') Or  IsNamedPolygon('D2_1') Or  IsNamedPolygon('C4_1') Or  IsNamedPolygon('C4_1') Or  IsNamedPolygon('C2_2') Or  IsNamedPolygon('GND') Or  IsNamedPolygon('C33_1') Or  IsNamedPolygon('C9_1')] p13: connectstyle=Direct reliefconductorwidth=10 reliefentries=4 polygonreliefangle="90 Angle" airgapwidth=10
PolygonConnect PolygonConnect_3 [All vs IsNamedPolygon('C28_1') Or  IsNamedPolygon('C12_2') Or  IsNamedPolygon('C28_1') Or  IsNamedPolygon('C9_1') Or  IsNamedPolygon('D5_2') Or  IsNamedPolygon('C12_2') Or  IsNamedPolygon('C2_2') Or  IsNamedPolygon('C14_1') Or  IsNamedPolygon('C4_1') Or  IsNamedPolygon('C14_1') Or  IsNamedPolygon('D6_2') Or  IsNamedPolygon('GND2') Or  IsNamedPolygon('Q1_3') Or  IsNamedPolygon('C5_1') Or  IsNamedPolygon('D2_1') Or  IsNamedPolygon('C4_1') Or  IsNamedPolygon('C13_1') Or  IsNamedPolygon('C5_1') Or  IsNamedPolygon('C13_1') Or  IsNamedPolygon('C33_1') Or  IsNamedPolygon('D2_1') Or  IsNamedPolygon('GND') Or  IsNamedPolygon('GND') Or  IsNamedPolygon('GND2') Or  IsNamedPolygon('C2_2') Or  IsNamedPolygon('C6_1') Or  IsNamedPolygon('C21_1')] p14: connectstyle=Direct reliefconductorwidth=10 reliefentries=4 polygonreliefangle="90 Angle" airgapwidth=10
PolygonConnect PolygonConnect_2 [All vs IsNamedPolygon('C21_1') Or  IsNamedPolygon('C4_1') Or  IsNamedPolygon('D5_2') Or  IsNamedPolygon('C5_1') Or  IsNamedPolygon('C14_1') Or  IsNamedPolygon('C13_1') Or  IsNamedPolygon('C4_1') Or  IsNamedPolygon('C33_1') Or  IsNamedPolygon('C12_2') Or  IsNamedPolygon('D2_1') Or  IsNamedPolygon('C2_2') Or  IsNamedPolygon('C28_1') Or  IsNamedPolygon('C12_2') Or  IsNamedPolygon('D2_1') Or  IsNamedPolygon('C5_1') Or  IsNamedPolygon('Q1_3') Or  IsNamedPolygon('GND') Or  IsNamedPolygon('D6_2') Or  IsNamedPolygon('C6_1') Or  IsNamedPolygon('C2_2') Or  IsNamedPolygon('C14_1') Or  IsNamedPolygon('C28_1') Or  IsNamedPolygon('C13_1') Or  IsNamedPolygon('C9_1') Or  IsNamedPolygon('GND')] p15: connectstyle=Direct reliefconductorwidth=10 reliefentries=4 polygonreliefangle="90 Angle" airgapwidth=10
PolygonConnect PolygonConnect_1 [All vs IsNamedPolygon('C28_1') Or  IsNamedPolygon('D5_2') Or  IsNamedPolygon('C5_1') Or  IsNamedPolygon('C5_1') Or  IsNamedPolygon('D2_1') Or  IsNamedPolygon('C21_1') Or  IsNamedPolygon('C9_1') Or  IsNamedPolygon('C4_1') Or  IsNamedPolygon('C14_1') Or  IsNamedPolygon('C28_1') Or  IsNamedPolygon('C6_1') Or  IsNamedPolygon('C12_2') Or  IsNamedPolygon('C33_1') Or  IsNamedPolygon('C4_1') Or  IsNamedPolygon('C13_1') Or  IsNamedPolygon('C12_2') Or  IsNamedPolygon('D6_2') Or  IsNamedPolygon('C2_2') Or  IsNamedPolygon('C14_1') Or  IsNamedPolygon('D2_1') Or  IsNamedPolygon('C2_2') Or  IsNamedPolygon('C13_1')] p16: connectstyle=Direct reliefconductorwidth=10 reliefentries=4 polygonreliefangle="90 Angle" airgapwidth=10
PolygonConnect [All] p17: connectstyle=Direct reliefconductorwidth=10 reliefentries=4 polygonreliefangle="90 Angle" airgapwidth=10
RoutingLayers [All] p1: top layer_v5=TRUE mid layer 1_v5=TRUE mid layer 2_v5=TRUE mid layer 3_v5=TRUE mid layer 4_v5=TRUE mid layer 5_v5=FALSE mid layer 6_v5=FALSE bottom layer_v5=TRUE
RoutingVias ThermalPadVias [IsVia and not InNet('SGND')and not InNet('Vout')] p1: holewidth=7.87 width=19.68 viastyle="Through Hole" minholewidth=7.87 minwidth=19.68 maxholewidth=17 maxwidth=35
RoutingVias [IsVia and not InNet('SGND')and not InNet('Vout')] p2: holewidth=16 width=34 viastyle="Through Hole" minholewidth=7.87 minwidth=20 maxholewidth=40 maxwidth=65
SilkToBoardRegionClearance [Not ((IsComment or IsDesignator) And (Hide <> 'False')) and not InRegion(1000,500,4000,800)] p1:
SilkToSilkClearance SilkToSilkClearance_Pb-FreeLogo [(HasFootprint('Pb-Free_Overlay_Medium') OR HasFootprint('Pb-Free_Overlay_Small')) vs (HasFootprint('Pb-Free_Overlay_Medium') OR HasFootprint('Pb-Free_Overlay_Small'))] p1: silktosilkclearance=0
SilkToSilkClearance [All] p2: silktosilkclearance=3
SilkToSolderMaskClearance "Silk to Solder Mask Opening" [All] p1: minsilkscreentomaskgap=1 clearancetoexposedcopper=FALSE
SolderMaskExpansion [All] p1: expansion=1.97 istentingtop=FALSE
UnpouredPolygon [All] p1: allowunpoured=TRUE allowshelved=TRUE
Width [All] p1: maxlimit=100 minlimit=6 preferedwidth=10 checkconnectedcopper=TRUE
12 further rules are at their usual default settings.

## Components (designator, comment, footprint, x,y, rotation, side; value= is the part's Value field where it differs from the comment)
C1 "C1608X5R1H104K080AA" 0603L 452.18,1072.09 r0 bottom value=0.1uF
C2 "C0603C101J5GACTU" 0603L 561,1349.99 r180 bottom value=100pF
C3 "C0603C101J5GACTU" 0603L 423,1147.49 r270 bottom value=100pF
C4 "GRM188R71E103KA01D" 0603L 142.85,1006.49 r0 bottom value=0.01uF
D1 "MMSZ5245BS-7-F" SOD-323 691,1332.49 r180 bottom value=15V
D2 "BAS316,115" SOD-323 862,1332.49 r0 bottom value=100V
Q1 "CSD16570Q5B" DNK0008A#1 921.5,1165.47 r0 top value=25V
Q2 "CSD16570Q5B" DNK0008A#1 921.61,939.09 r0 top value=25V
Q3 "CSD16570Q5B" DNK0008A#1 920.91,709.56 r0 top value=25V
Q4 "CSD16570Q5B" DNK0008A#1 921.61,486.33 r0 top value=25V
Q5 "CSD16570Q5B" DNK0008A#2 917.5,1163.15 r0 bottom value=25V
Q6 "CSD16570Q5B" DNK0008A#2 917.61,936.77 r0 bottom value=25V
Q7 "CSD16570Q5B" DNK0008A#2 916.91,707.25 r0 bottom value=25V
Q8 "CSD16570Q5B" DNK0008A#2 917.61,484.02 r0 bottom value=25V
Q9 "CSD16570Q5B" DNK0008A#1 922.78,263.95 r0 top value=25V
Q10 "CSD16570Q5B" DNK0008A#2 918.78,261.64 r0 bottom value=25V
R1 "CRCW04025K11FKED" 0402L 566,1299.49 r0 bottom value=5.11k
R2 "RC0402FR-0710KL" 0402L 214.28,1344.49 r90 bottom value=10.0k
R3 "MCR01MZPF10R0" 0402L 142.85,954.49 r0 bottom value=10.0
R4 "RC0402FR-0710KL" 0402L 148.44,1330.51 r180 bottom value=10.0k
R5 "RC0402FR-07100KL" 0402L 211.97,991 r270 bottom value=100k
R6 "RC0402FR-0710KL" 0402L 80.65,1197.17 r270 bottom value=10.0k
R7 "CRCW0402549RFKED" 0402L 148.44,1279.33 r0 bottom value=549
R8 "WSLP20101L000FEA" WSLP2010-001 602.77,212.11 r0 top value=0.001
R9 "WSLP20101L000FEA" WSLP2010-001 602.77,337.68 r0 top value=0.001
R10 "WSLP20101L000FEA" WSLP2010-001 602.77,460.11 r0 top value=0.001
R11 "WSLP20101L000FEA" WSLP2010-001 602.77,581.11 r0 top value=0.001
R12 "WSLP20101L000FEA" WSLP2010-001 602.77,702.11 r0 top value=0.001
R13 "WSLP20101L000FEA" WSLP2010-001 602.77,823.17 r0 top value=0.001
R14 "WSLP20101L000FEA" WSLP2010-001 602.77,946.17 r0 top value=0.001
R15 "WSLP20101L000FEA" WSLP2010-001 602.77,1066.17 r0 top value=0.001
R16 "WSLP20101L000FEA" WSLP2010-001 602.77,1187.17 r0 top value=0.001
R17 "WSLP20101L000FEA" WSLP2010-001 602.77,1309.94 r0 top value=0.001
U1 "TPS2411PWR" PW0014A_L 235.05,1145.99 r0 bottom

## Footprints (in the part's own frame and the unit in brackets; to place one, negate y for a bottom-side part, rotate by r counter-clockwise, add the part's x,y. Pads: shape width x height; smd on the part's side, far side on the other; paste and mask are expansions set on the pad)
0402L [mm] "0402 from SM-752 data"
  rect 0.6x0.5 smd: 1(-0.5,0) 2(0.5,0)
  body extent -0.55,-0.3 0.55,0.3, height 0.6
0603L [mm] "0603 from SM-752 data"
  rect 0.8x0.85 smd: 1(-0.7,0) 2(0.7,0)
  silkscreen extent -0.07,-0.33 0.07,0.33, body extent -0.87,-0.47 0.87,0.47, height 1
DNK0008A#1 [mm] "SON, 8-Leads, Body 5x6mm"
  rrect39% 0.86x0.51 smd paste-0.05 mask-0.05: 1(-2.82,1.905) 2(-2.82,0.635) 3(-2.82,-0.635) 4(-2.82,-1.905) 5(2.82,-1.905) 6(2.82,-0.635) 7(2.82,0.635) 8(2.82,1.905)
  rrect40% 0.25x0.555 on Top Solder: 9(-0.83,-2.372) 9(-0.83,2.372)
  rrect40% 0.25x0.555 on Top Paste: 9(-0.83,-2.372) 9(-0.83,2.372)
  rrect11% 0.95x1.13 on Top Paste: 9(-0.535,-1.33) 9(-0.535,0) 9(-0.535,1.33) 9(0.615,-1.33) 9(0.615,0) 9(0.615,1.33) 9(1.765,-1.33) 9(1.765,0) 9(1.765,1.33)
  rrect3% 3.58x4 on Top Solder: 9(0.75,0)
  rrect5% 4.34x5.4 smd paste-3 mask-3: 9(1.08,0)
  body extent -3.05,-2.55 3.05,2.55, height 1.06
DNK0008A#2 [mm] "SON, 8-Leads, Body 5x6mm"
  rrect39% 0.86x0.51 smd paste-0.05 mask-0.05: 1(-2.82,1.905) 2(-2.82,0.635) 3(-2.82,-0.635) 4(-2.82,-1.905) 5(2.82,-1.905) 6(2.82,-0.635) 7(2.82,0.635) 8(2.82,1.905)
  rrect40% 0.25x0.555 on Bottom Solder: 9(-0.83,-2.372) 9(-0.83,2.372)
  rrect40% 0.25x0.555 on Bottom Paste: 9(-0.83,-2.372) 9(-0.83,2.372)
  rrect11% 0.95x1.13 on Bottom Paste: 9(-0.535,-1.33) 9(-0.535,0) 9(-0.535,1.33) 9(0.615,-1.33) 9(0.615,0) 9(0.615,1.33) 9(1.765,-1.33) 9(1.765,0) 9(1.765,1.33)
  rrect3% 3.58x4 on Bottom Solder: 9(0.75,0)
  rrect5% 4.34x5.4 smd paste-3 mask-3: 9(1.08,0)
  body extent -3.05,-2.55 3.05,2.55, height 1.06
PW0014A_L [mm] "TSOP, 14-Leads, Body 5x4.4mm, Pitch 0.65mm, IPC High Density"
  oval 1.2x0.4 smd: 1(-2.85,1.95) 2(-2.85,1.3) 3(-2.85,0.65) 4(-2.85,0) 5(-2.85,-0.65) 6(-2.85,-1.3) 7(-2.85,-1.95) 8(2.85,-1.95) 9(2.85,-1.3) 10(2.85,-0.65) 11(2.85,0) 12(2.85,0.65) 13(2.85,1.3) 14(2.85,1.95)
  silkscreen extent -3.2,-2.55 1.85,2.55, body extent -3.21,-2.5 3.21,2.5, height 1
SOD-323 [mm] "NXP recommended land pattern"
  rect 0.6x0.6 smd paste-0.05: 1(-1.1,0) 2(1.1,0)
  silkscreen extent -2.06,-0.86 1.53,0.86, body extent -1.3,-0.67 1.3,0.68, height 1.1
WSLP2010-001 [mm] "Vishay"
  rrect4% 2.36x3.05 smd: 1(-1.88,0) 2(1.88,0)
  silkscreen extent -0.4,-1.5 0.4,1.5, body extent -2.54,-1.27 2.54,1.27, height 0.66

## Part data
C1: library part CMP-0007010-5, "CAP, CERM, 0.1 uF, 50 V, +/- 10%, X5R, 0603", Cap_Case=0603, Manufacturer=TDK, Supplier Part Number 1=445-7456-1-ND, Tempco=X5R, Tolerance_%=10%, Value1="0.0296 ohm", Value2=50V, ValueDisplayed=0.1uF
C2 C3: library part CMP-0006841-4, "CAP, CERM, 100 pF, 50 V, +/- 5%, C0G/NP0, 0603", Cap_Case=0603, Manufacturer=Kemet, Supplier Part Number 1=399-1061-1-ND, Tempco=C0G/NP0, Tolerance_%=5%, Value1=Unknown, Value2=50V, ValueDisplayed=100pF
C4: library part CMP-0007403-4, "CAP, CERM, 0.01 uF, 25 V, +/- 10%, X7R, 0603", Cap_Case=0603, Manufacturer=MuRata, Supplier Part Number 1=490-1520-1-ND, Tempco=X7R, Tolerance_%=10%, Value1=Unknown, Value2=25V, ValueDisplayed=0.01uF
D1: library part CMP-0005833-4, "Diode, Zener, 15 V, 200 mW, SOD-323", Manufacturer="Diodes Inc.", Power_W=200mW, Value1=0.2W
D2: library part CMP-0029006-2, "Diode, Ultrafast, 100 V, 0.25 A, SOD-323", Manufacturer=Nexperia, Value1=0.25A, Value2=1.4V
Q1 Q2 Q3 Q4 Q5 Q6 Q7 Q8 Q9 Q10: library part CMP-0000274-2, "MOSFET, N-CH, 25 V, 100 A, DNK0008A (VSON-CLIP-8)", Alternate Manufacturer=None, Manufacturer="Texas Instruments", Supplier Part Number 1=CSD16570Q5B-ND, Value1=0, Value2="192 nC"
R1: library part CMP-0026463-2, "RES, 5.11 k, 1%, 0.063 W, AEC-Q200 Grade 0, 0402", Manufacturer=Vishay-Dale, Power_W=63mW, Supplier Part Number 1=541-5.11KLCT-ND, Tempco="100 ppm/C", Tolerance_%=1%, Value2=0.063W, Value_Code=5k11, ValueDisplayed=5.11k
R2 R4 R6: library part CMP-0078669-1, "RES, 10.0 k, 1%, 0.063 W, 0402", Manufacturer="Yageo America", Power_W=63mW, Supplier Part Number 1=311-10.0KLRCT-ND, Tempco="100 ppm/C", Tolerance_%=1%, Value2=0.063W, Value_Code=10k0, ValueDisplayed=10.0k
R3: library part CMP-0026717-1, "RES, 10.0, 1%, 0.063 W, 0402", Manufacturer=Rohm, Power_W=63mW, Supplier Part Number 1=RHM10.0LCT-ND, Tempco="100 ppm/C", Tolerance_%=1%, Value2=0.063W, Value_Code=10R0, ValueDisplayed=10.0
R5: library part CMP-0026721-1, "RES, 100 k, 1%, 0.0625 W, 0402", Manufacturer="Yageo America", Power_W=62.5mW, Supplier Part Number 1=311-100KLRCT-ND, Tempco="100 ppm/C", Tolerance_%=1%, Value2=0.0625W, Value_Code=100k
R7: library part CMP-0026448-2, "RES, 549, 1%, 0.063 W, AEC-Q200 Grade 0, 0402", Manufacturer=Vishay-Dale, Power_W=63mW, Supplier Part Number 1=541-549LCT-ND, Tempco="100 ppm/C", Tolerance_%=1%, Value2=0.063W, Value_Code=549R, ValueDisplayed=549
R8 R9 R10 R11 R12 R13 R14 R15 R16 R17: library part CMP-0016564-3, "RES, 0.001, 1%, 2 W, 2010", Manufacturer=Vishay-Dale, Power_W=2W, Supplier Part Number 1=54X6168, Tempco="275 ppm/C", Tolerance_%=1%, Value_Code=1L000, ValueDisplayed=0.001
U1: library part CMP-0038282-1, "N+1 and OR-ing Power Rail Controller, 0.8 to 16.5 V, -40 to 85 degC, 14-pin TSSOP (PW), Green (RoHS & no Sb/Br)", Manufacturer="Texas Instruments", Under/Over Voltage Reporting=Yes

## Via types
v1: diameter 24, hole 8, Top Layer to Bottom Layer, 1004 vias
v2: diameter 24, hole 8, Top Layer to Bottom Layer, tented both sides, 18 vias
v3: diameter 20, hole 10, Top Layer to Bottom Layer, 1 vias

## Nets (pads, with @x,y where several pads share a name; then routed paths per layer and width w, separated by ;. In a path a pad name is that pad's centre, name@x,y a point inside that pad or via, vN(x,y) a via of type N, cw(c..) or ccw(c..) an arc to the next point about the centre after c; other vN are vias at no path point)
12VA: C1.2 C3.1 D1.2 Q1.1 Q1.2 Q1.3 Q2.1 Q2.2 Q2.3 Q3.1 Q3.2 Q3.3 Q4.1 Q4.2 Q4.3 Q5.1 Q5.2 Q5.3 Q6.1 Q6.2 Q6.3 Q7.1 Q7.2 Q7.3 Q8.1 Q8.2 Q8.3 Q9.1 Q9.2 Q9.3 Q10.1 Q10.2 Q10.3 R2.2 R4.2 R8.2 R9.2 R10.2 R11.2 R12.2 R13.2 R14.2 R15.2 R16.2 R17.2 U1.11 | length 3260
  Top Layer w12: 41,165.87 43.14,168 43.14,234 54.95,245.82 v2(54.95,303.34)
  Layer 2 w12: v2(175,1365.49) 175,1211.71 v2(228.87,1157.84)
  Layer 3 w12: v2(54.95,303.34) 54.95,373.78 85.01,403.84 85.01,1062.4 150.62,1128 575.54,1128 609.87,1093.66 609.87,806 617.94,797.93 ; v2@228.87,1161.08 v2(228.87,1157.84) 240.72,1145.99 584.01,1145.99 629.71,1100.29 629.71,809.69 617.94,797.93 ; v2(617.94,750) 617.94,797.93
  Bottom Layer w12: R4.2@128.75,1330.51 128.75,1344.29 147.65,1363.19 172.7,1363.19 v2(175,1365.49) 175.66,1364.83 213.62,1364.83 R2.2@214.28,1364.18 ; v2(228.87,1157.84) 230.05,1157.84 241.9,1145.99 U1.11@347.25,1145.99 382.66,1145.99 401.97,1165.3 413.25,1165.3 C3.1@423,1175.05 457.97,1175.05 479.74,1153.28 C1.2@479.74,1083.6 ; C1.2@479.74,1072.09 480.13,1072.49 C1.2@480.13,1083.6
  other v1: 660,26 686,26 712,26 738,26 764,26 790,26 816,26 842,26 673,52 699,52 725,52 751,52 777,52 803,52 829,52 855,52 660,78 686,78 712,78 738,78 764,78 790,78 816,78 842,78 673,104 699,104 725,104 751,104 777,104 803,104 829,104 855,104 660,130 686,130 712,130 738,130 764,130 751,156 751,208 764,234 751,260 764,286 751,312 764,338 751,364 764,390 751,416 764,442 751,468 764,494 751,520 764,546 751,572 764,598 751,624 751.29,651.2 751,676 764,754 748.86,780 764,806 751,832 751,884 764,910 751,936 764,962 751,988 764,1014 751,1040 764,1073.3 750,1102.64 764,1133.15 750,1166.34
12VB: C2.1 Q1.5 Q1.6 Q1.7 Q1.8 Q1.9@964.02,1165.47 Q2.5 Q2.6 Q2.7 Q2.8 Q2.9@964.13,939.09 Q3.5 Q3.6 Q3.7 Q3.8 Q3.9@963.43,709.56 Q4.5 Q4.6 Q4.7 Q4.8 Q4.9@964.13,486.33 Q5.5 Q5.6 Q5.7 Q5.8 Q5.9@960.02,1163.15 Q6.5 Q6.6 Q6.7 Q6.8 Q6.9@960.13,936.77 Q7.5 Q7.6 Q7.7 Q7.8 Q7.9@959.43,707.25 Q8.5 Q8.6 Q8.7 Q8.8 Q8.9@960.13,484.02 Q9.5 Q9.6 Q9.7 Q9.8 Q9.9@965.3,263.95 Q10.5 Q10.6 Q10.7 Q10.8 Q10.9@961.3,261.64 R1.2 | length 1001
  Top Layer w10: v2(849,710) 849.44,709.56 868.21,709.56
  Layer 3 w20: v3@590,1266.98 590,1173.76 653.58,1110.18 653.58,746.5 690.08,710 v2(849,710)
  Bottom Layer w10: Q7.9@890,710 956.67,710 Q7.9@959.43,707.25
  Bottom Layer w12: R1.2@585.69,1299.49 R1.2@587.12,1300.93 ; Q5.9@960.02,1163.15 Q5.9@960.02,1184.02
  Bottom Layer w20: C2.1@590,1348.55 C2.1@588.56,1349.99 588.56,1296.62 600,1285.18 v3(600,1266.98) ; v2(849,710) Q7.9@890,710
  other v1: 972,26 998,26 1024,26 1050,26 1076,26 1102,26 1128,26 1154,26 1180,26 1206,26 1232,26 1258,26 1284,26 1310,26 985,52 1011,52 1037,52 1063,52 1089,52 1115,52 1141,52 1167,52 1193,52 1219,52 1245,52 1271,52 1297,52 1323,52 972,78 998,78 1024,78 1050,78 1076,78 1102,78 1128,78 1154,78 1180,78 1206,78 1232,78 1258,78 1284,78 1310,78 985,104 1011,104 1037,104 1063,104 1089,104 1115,104 1141,104 1167,104 1193,104 1219,104 1245,104 1271,104 1297,104 1323,104 972,130 998,130 1024,130 1050,130 1076,130 1102,130 1128,130 1154,130 1180,130 1206,130 1232,130 1258,130 1284,130 1310,130 1089,156 1115,156 1141,156 1167,156 1193,156 1219,156 1245,156 1271,156 1297,156 1323,156 1076,182 1102,182 1128,182 1154,182 1180,182 1206,182 1232,182 1258,182 1284,182 1310,182 1089,208 1115,208 1141,208 1167,208 1193,208 1219,208 1245,208 1271,208 1297,208 1323,208 1076,234 1102,234 1128,234 1154,234 1180,234 1206,234 1232,234 1258,234 1284,234 1310,234 1089,260 1115,260 1141,260 1167,260 1193,260 1219,260 1245,260 1271,260 1297,260 1323,260 1076,286 1102,286 1128,286 1154,286 1180,286 1206,286 1232,286 1258,286 1284,286 1310,286 1089,312 1115,312 1141,312 1167,312 1193,312 1219,312 1245,312 1271,312 1297,312 1323,312 1076,338 1102,338 1128,338 1154,338 1180,338 1206,338 1232,338 1258,338 1284,338 1310,338 1089,364 1115,364 1141,364 1167,364 1193,364 1219,364 1245,364 1271,364 1297,364 1323,364 1076,390 1102,390 1128,390 1154,390 1180,390 1206,390 1232,390 1258,390 1284,390 1310,390 1089,416 1115,416 1141,416 1167,416 1193,416 1219,416 1245,416 1271,416 1297,416 1323,416 1076,442 1102,442 1128,442 1154,442 1180,442 1206,442 1232,442 1258,442 1284,442 1310,442 1089,468 1115,468 1141,468 1167,468 1193,468 1219,468 1245,468 1271,468 1297,468 1323,468 1076,494 1102,494 1128,494 1154,494 1180,494 1206,494 1232,494 1258,494 1284,494 1310,494 1089,520 1115,520 1141,520 1167,520 1193,520 1219,520 1245,520 1271,520 1297,520 1323,520 1076,546 1102,546 1128,546 1154,546 1180,546 1206,546 1232,546 1258,546 1284,546 1310,546 1089,572 1115,572 1141,572 1167,572 1193,572 1219,572 1245,572 1271,572 1297,572 1323,572 1076,598 1102,598 1128,598 1154,598 1180,598 1206,598 1232,598 1258,598 1284,598 1310,598 1089,624 1115,624 1141,624 1167,624 1193,624 1219,624 1245,624 1271,624 1297,624 1323,624 1076,650 1102,650 1128,650 1154,650 1180,650 1206,650 1232,650 1258,650 1284,650 1310,650 1089,676 1115,676 1141,676 1167,676 1193,676 1219,676 1245,676 1271,676 1297,676 1323,676 1076,702 1102,702 1128,702 1154,702 1180,702 1206,702 1232,702 1258,702 1284,702 1310,702 1089,728 1115,728 1141,728 1167,728 1193,728 1219,728 1245,728 1271,728 1297,728 1323,728 1076,754 1102,754 1128,754 1154,754 1180,754 1206,754 1232,754 1258,754 1284,754 1310,754 1089,780 1115,780 1141,780 1167,780 1193,780 1219,780 1245,780 1271,780 1297,780 1323,780 1076,806 1102,806 1128,806 1154,806 1180,806 1206,806 1232,806 1258,806 1284,806 1310,806 1089,832 1115,832 1141,832 1167,832 1193,832 1219,832 1245,832 1271,832 1297,832 1323,832 1076,858 1102,858 1128,858 1154,858 1180,858 1206,858 1232,858 1258,858 1284,858 1310,858 1089,884 1115,884 1141,884 1167,884 1193,884 1219,884 1245,884 1271,884 1297,884 1323,884 1076,910 1102,910 1128,910 1154,910 1180,910 1206,910 1232,910 1258,910 1284,910 1310,910 1089,936 1115,936 1141,936 1167,936 1193,936 1219,936 1245,936 1271,936 1297,936 1323,936 1076,962 1102,962 1128,962 1154,962 1180,962 1206,962 1232,962 1258,962 1284,962 1310,962 1089,988 1115,988 1141,988 1167,988 1193,988 1219,988 1245,988 1271,988 1297,988 1323,988 1076,1014 1102,1014 1128,1014 1154,1014 1180,1014 1206,1014 1232,1014 1258,1014 1284,1014 1310,1014 1089,1040 1115,1040 1141,1040 1167,1040 1193,1040 1219,1040 1245,1040 1271,1040 1297,1040 1323,1040 1076,1066 1102,1066 1128,1066 1154,1066 1180,1066 1206,1066 1232,1066 1258,1066 1284,1066 1310,1066 1089,1092 1115,1092 1141,1092 1167,1092 1193,1092 1219,1092 1245,1092 1271,1092 1297,1092 1323,1092 1076,1118 1102,1118 1128,1118 1154,1118 1180,1118 1206,1118 1232,1118 1258,1118 1284,1118 1310,1118 1089,1144 1115,1144 1141,1144 1167,1144 1193,1144 1219,1144 1245,1144 1271,1144 1297,1144 1323,1144 1076,1170 1102,1170 1128,1170 1154,1170 1180,1170 1206,1170 1232,1170 1258,1170 1284,1170 1310,1170 1089,1196 1115,1196 1141,1196 1167,1196 1193,1196 1219,1196 1245,1196 1271,1196 1297,1196 1323,1196 1076,1222 1102,1222 1128,1222 1154,1222 1180,1222 1206,1222 1232,1222 1258,1222 1284,1222 1310,1222 1089,1248 1115,1248 1141,1248 1167,1248 1193,1248 1219,1248 1245,1248 1271,1248 1297,1248 1323,1248 1076,1274 1102,1274 1128,1274 1154,1274 1180,1274 1206,1274 1232,1274 1258,1274 1284,1274 1310,1274 959,1300 985,1300 1011,1300 1037,1300 1063,1300 1089,1300 1115,1300 1141,1300 1167,1300 1193,1300 1219,1300 1245,1300 1271,1300 1297,1300 1323,1300 972,1326 998,1326 1024,1326 1050,1326 1076,1326 1102,1326 1128,1326 1154,1326 1180,1326 1206,1326 1232,1326 1258,1326 1284,1326 959,1352 985,1352 1011,1352 1037,1352 1063,1352 1089,1352 1115,1352 1141,1352 1167,1352 1193,1352 1219,1352 1245,1352 1271,1352
12VS: R3.2 | length 809.1
  Bottom Layer w20: 104.89,172.14 101.97,175.05 101.97,313.27 162.54,373.84 R3.2@162.54,954.49 162.76,954.49 R3.2@162.92,954.33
